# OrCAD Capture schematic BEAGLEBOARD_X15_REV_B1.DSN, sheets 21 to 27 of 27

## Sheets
21 P22_DDR3 BANK 2: size B; title: BeagleBoard-X15 DDR BANK 2; note: BeagleBoard-X15_B.dsn
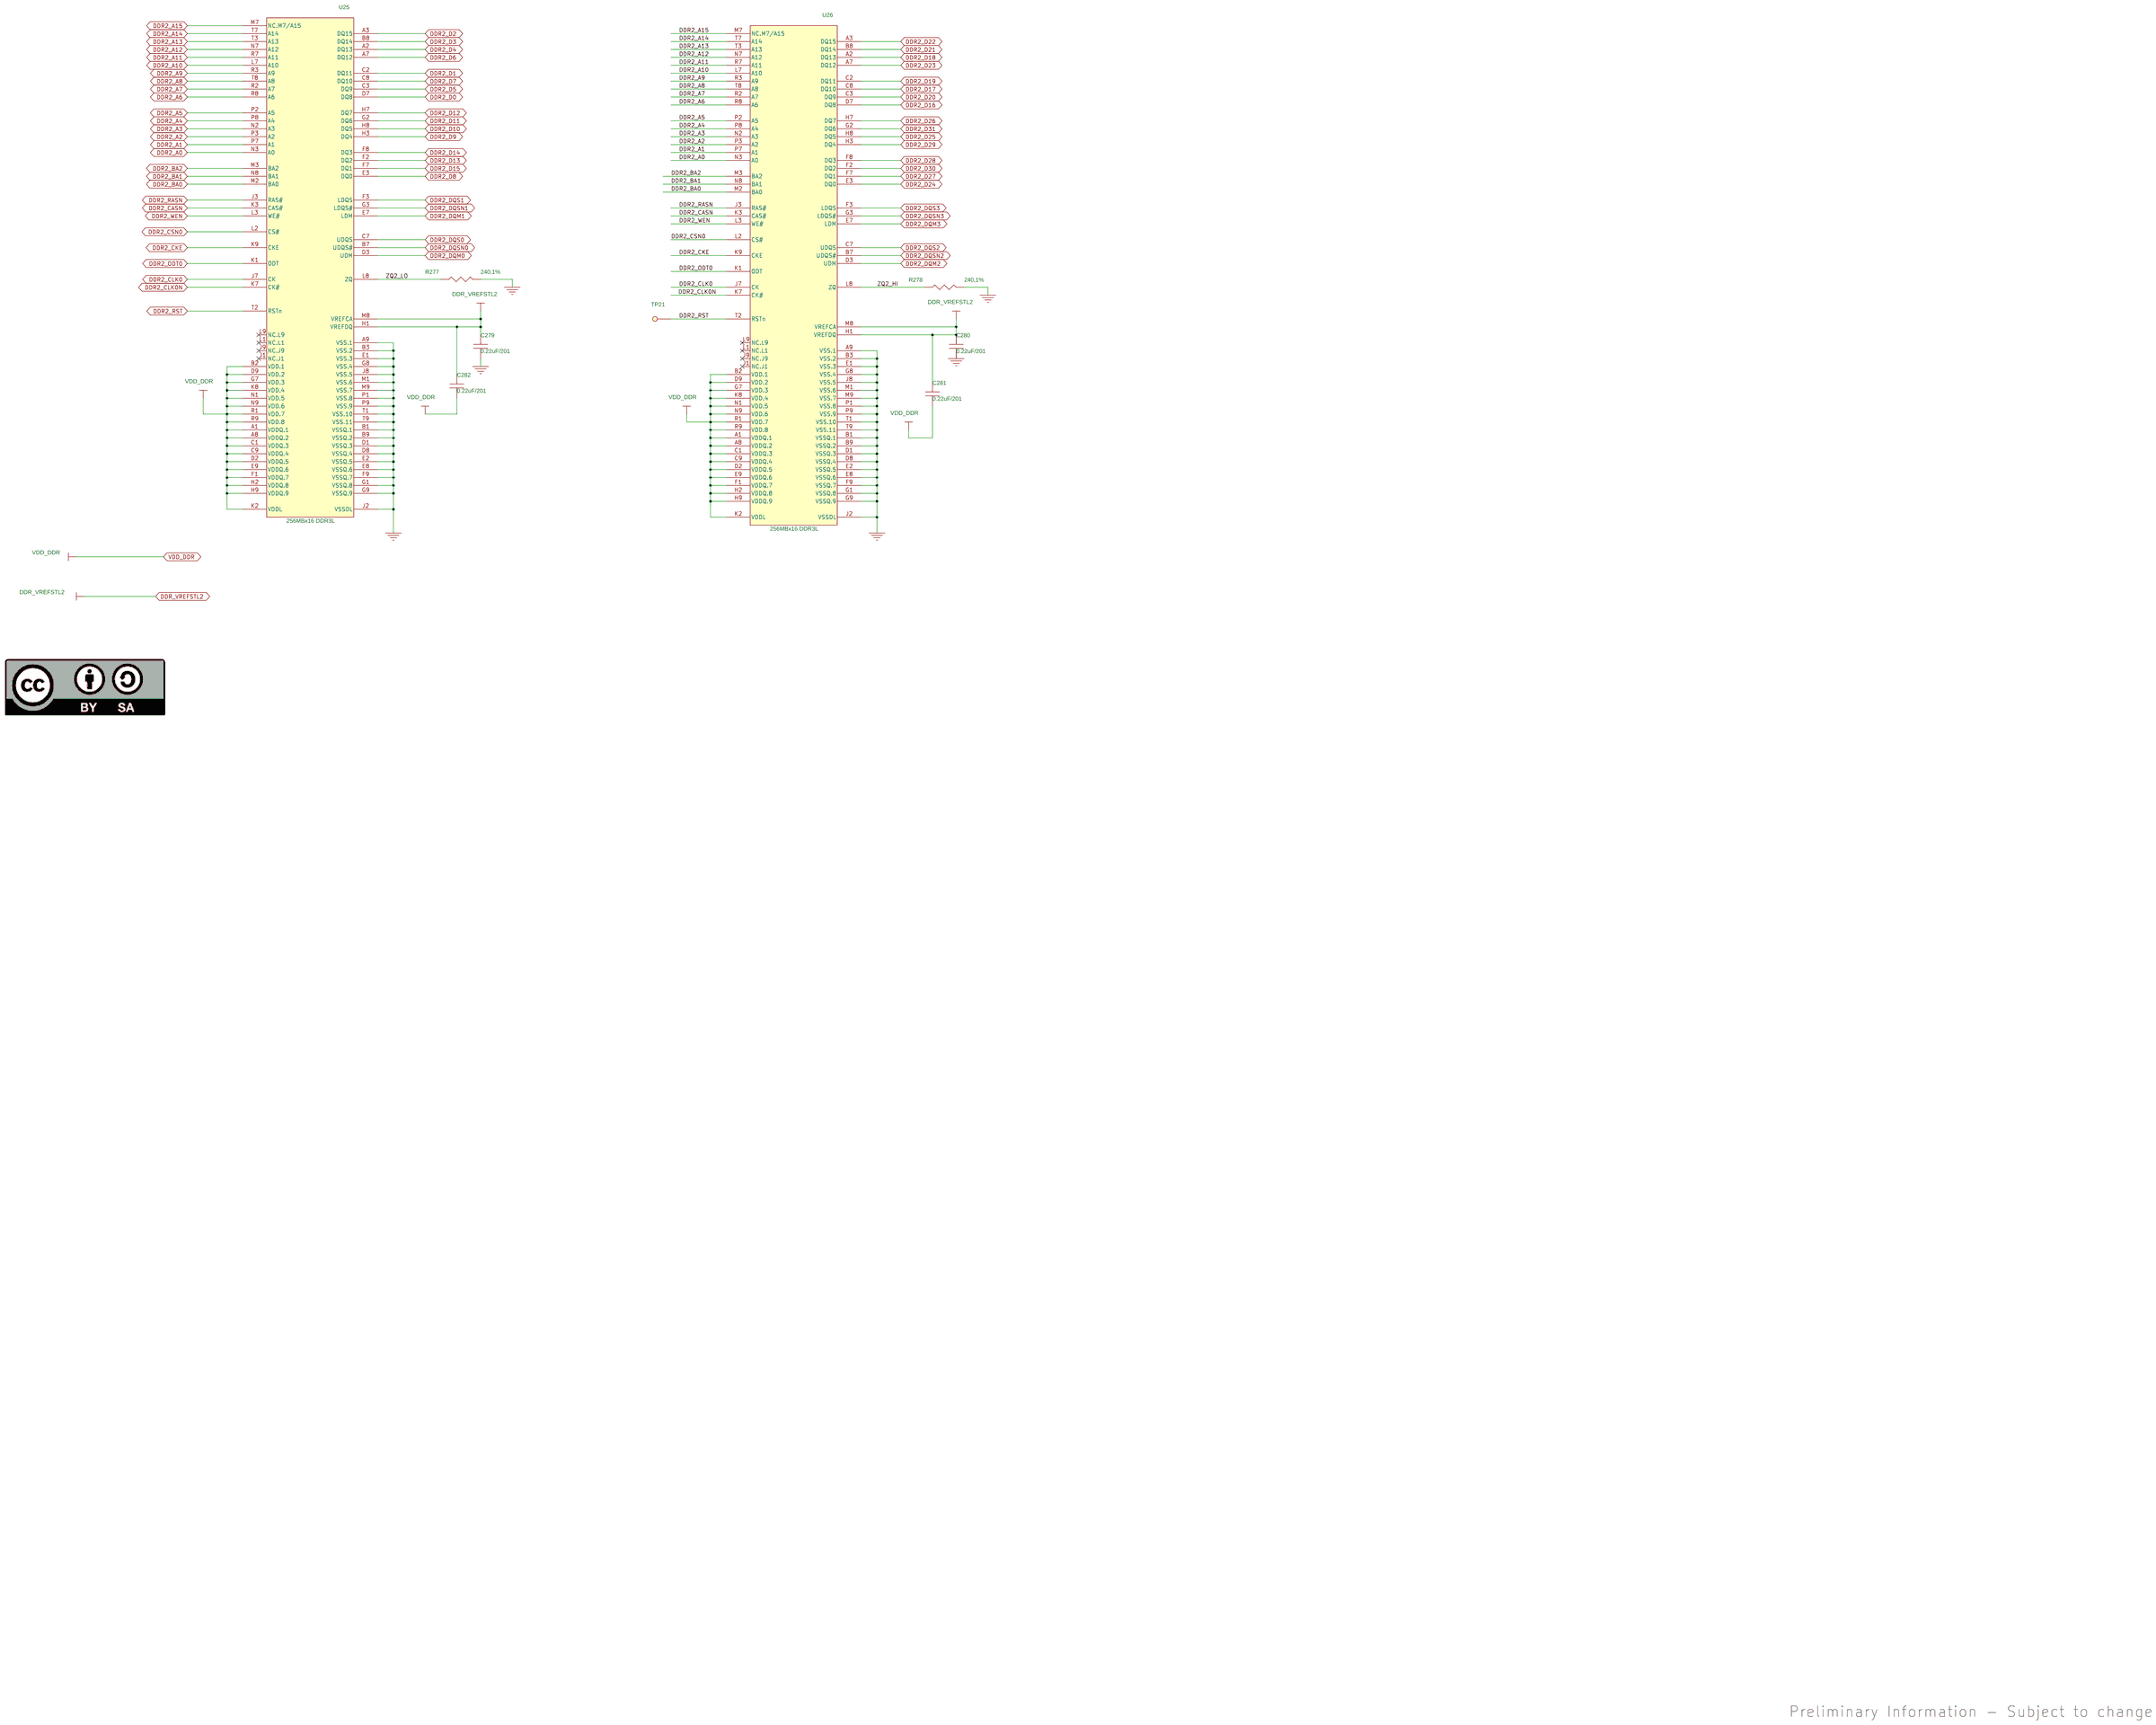
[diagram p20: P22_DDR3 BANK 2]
22 P23_DDR3 BANK 2 CAPS & TERM: size B; title: BEAGLEBOARD-X15 DDR3L BANK 2 CAPS AND TERMINATIONS; note: BeagleBoard-X15_B.dsn
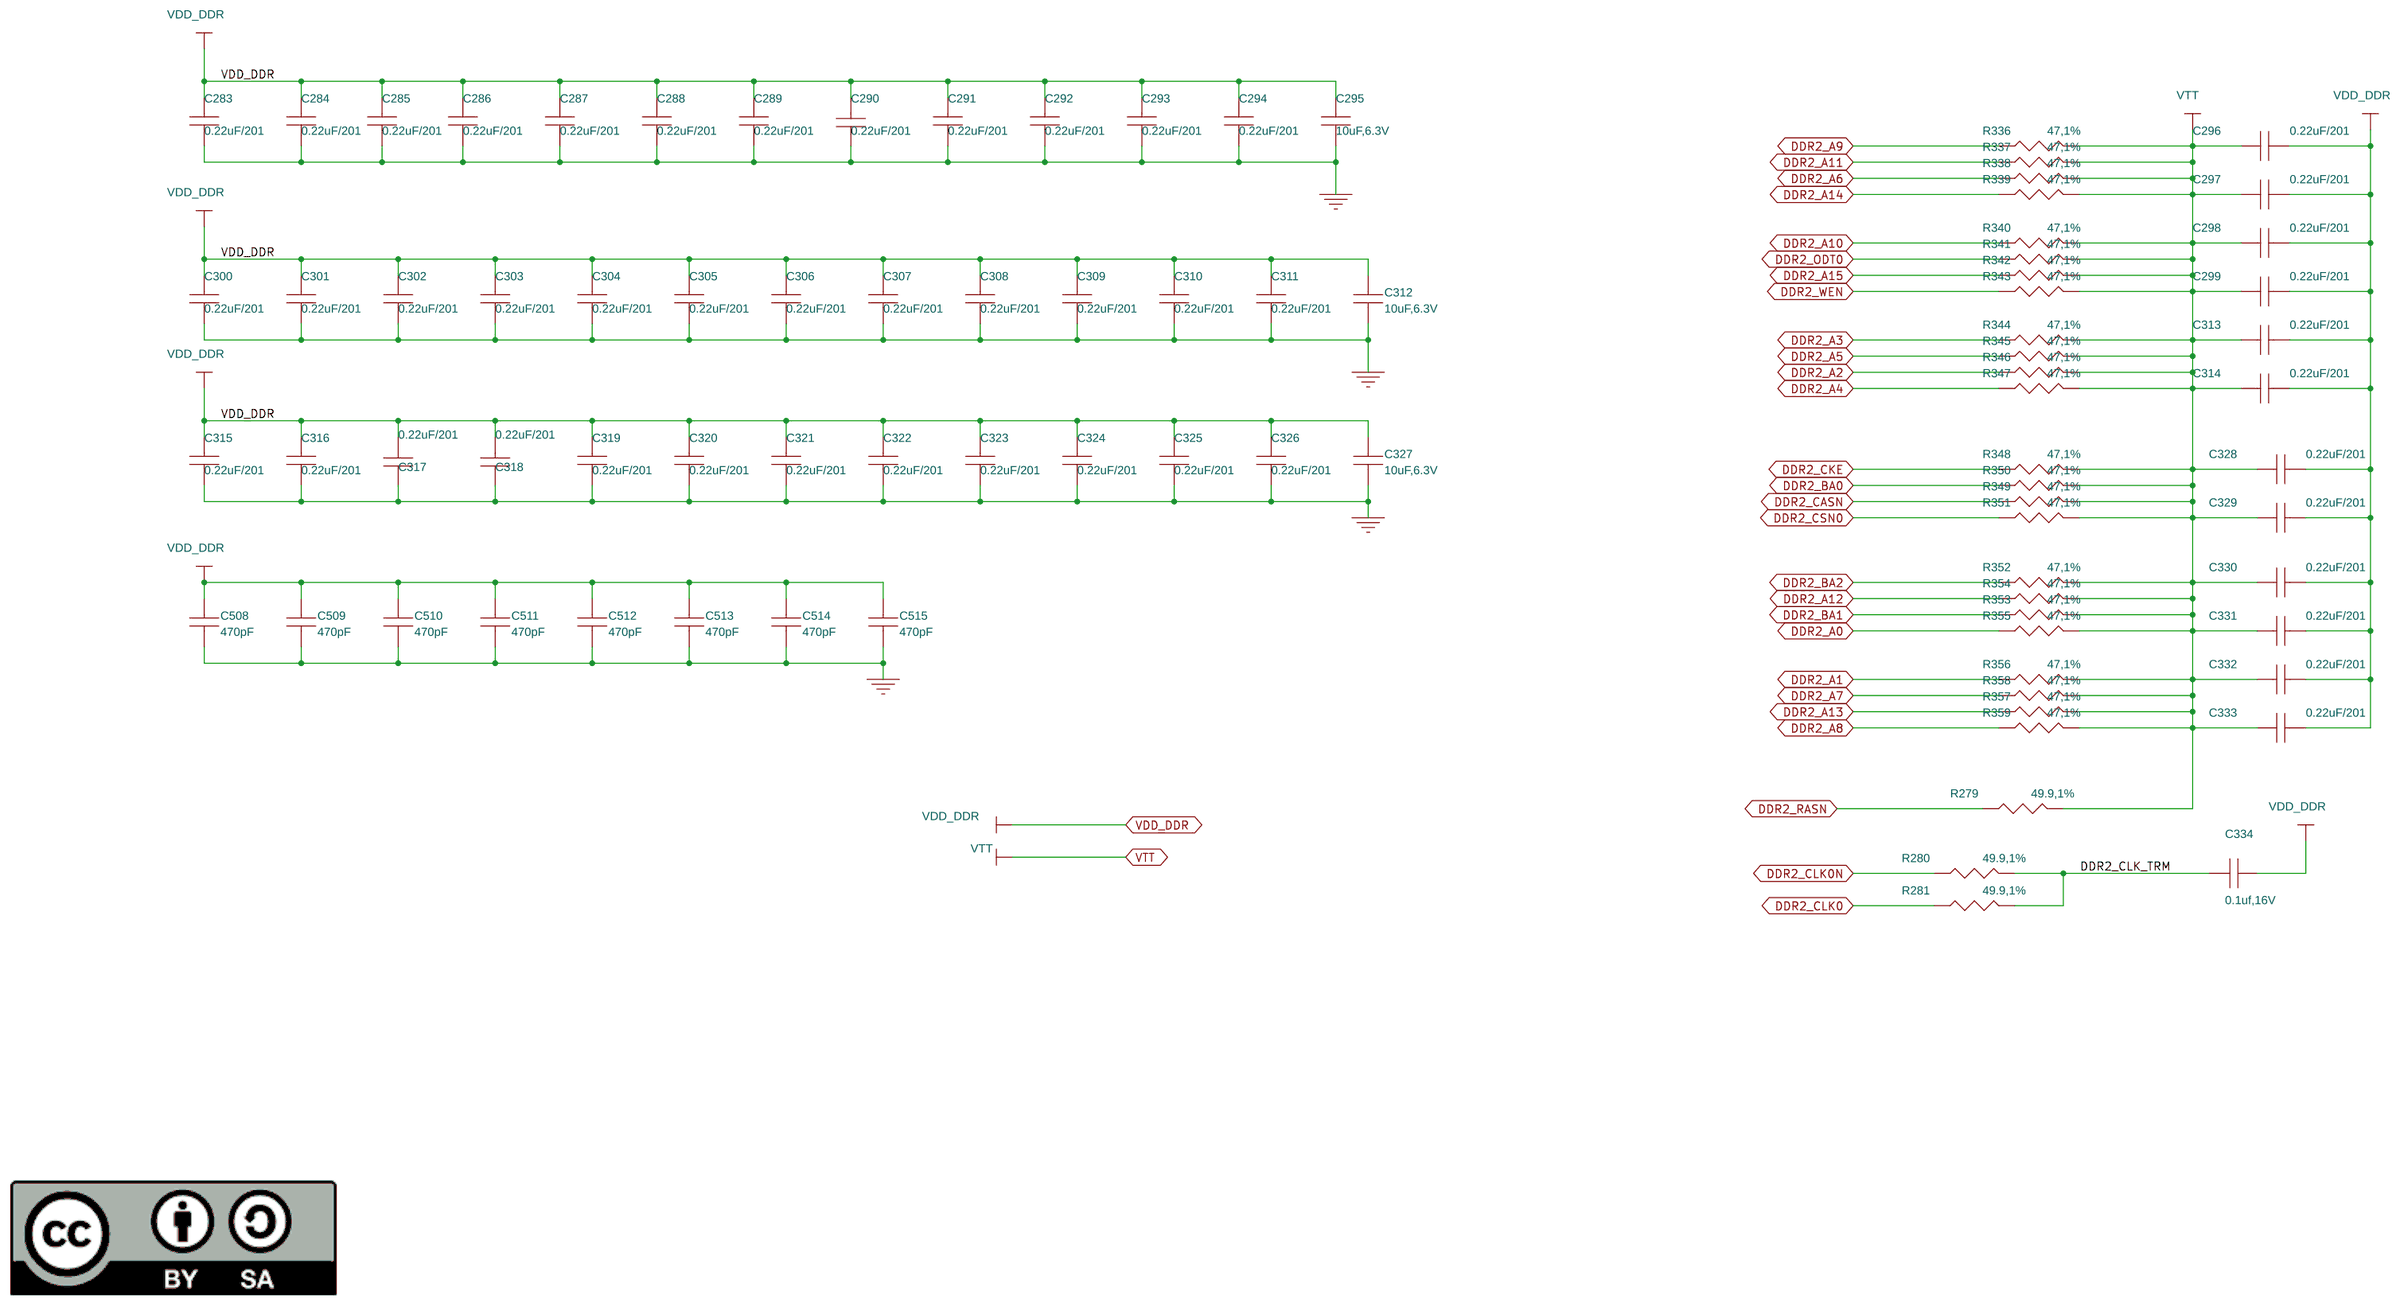
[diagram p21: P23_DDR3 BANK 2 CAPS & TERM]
23 P24_DDR3 BANK1 CAPS & TERM: size B; title: BEAGLEBOARD-X15 DDR3L BANK 1 CAPS AND TERMINATIONS; note: BeagleBoard-X15_B.dsn
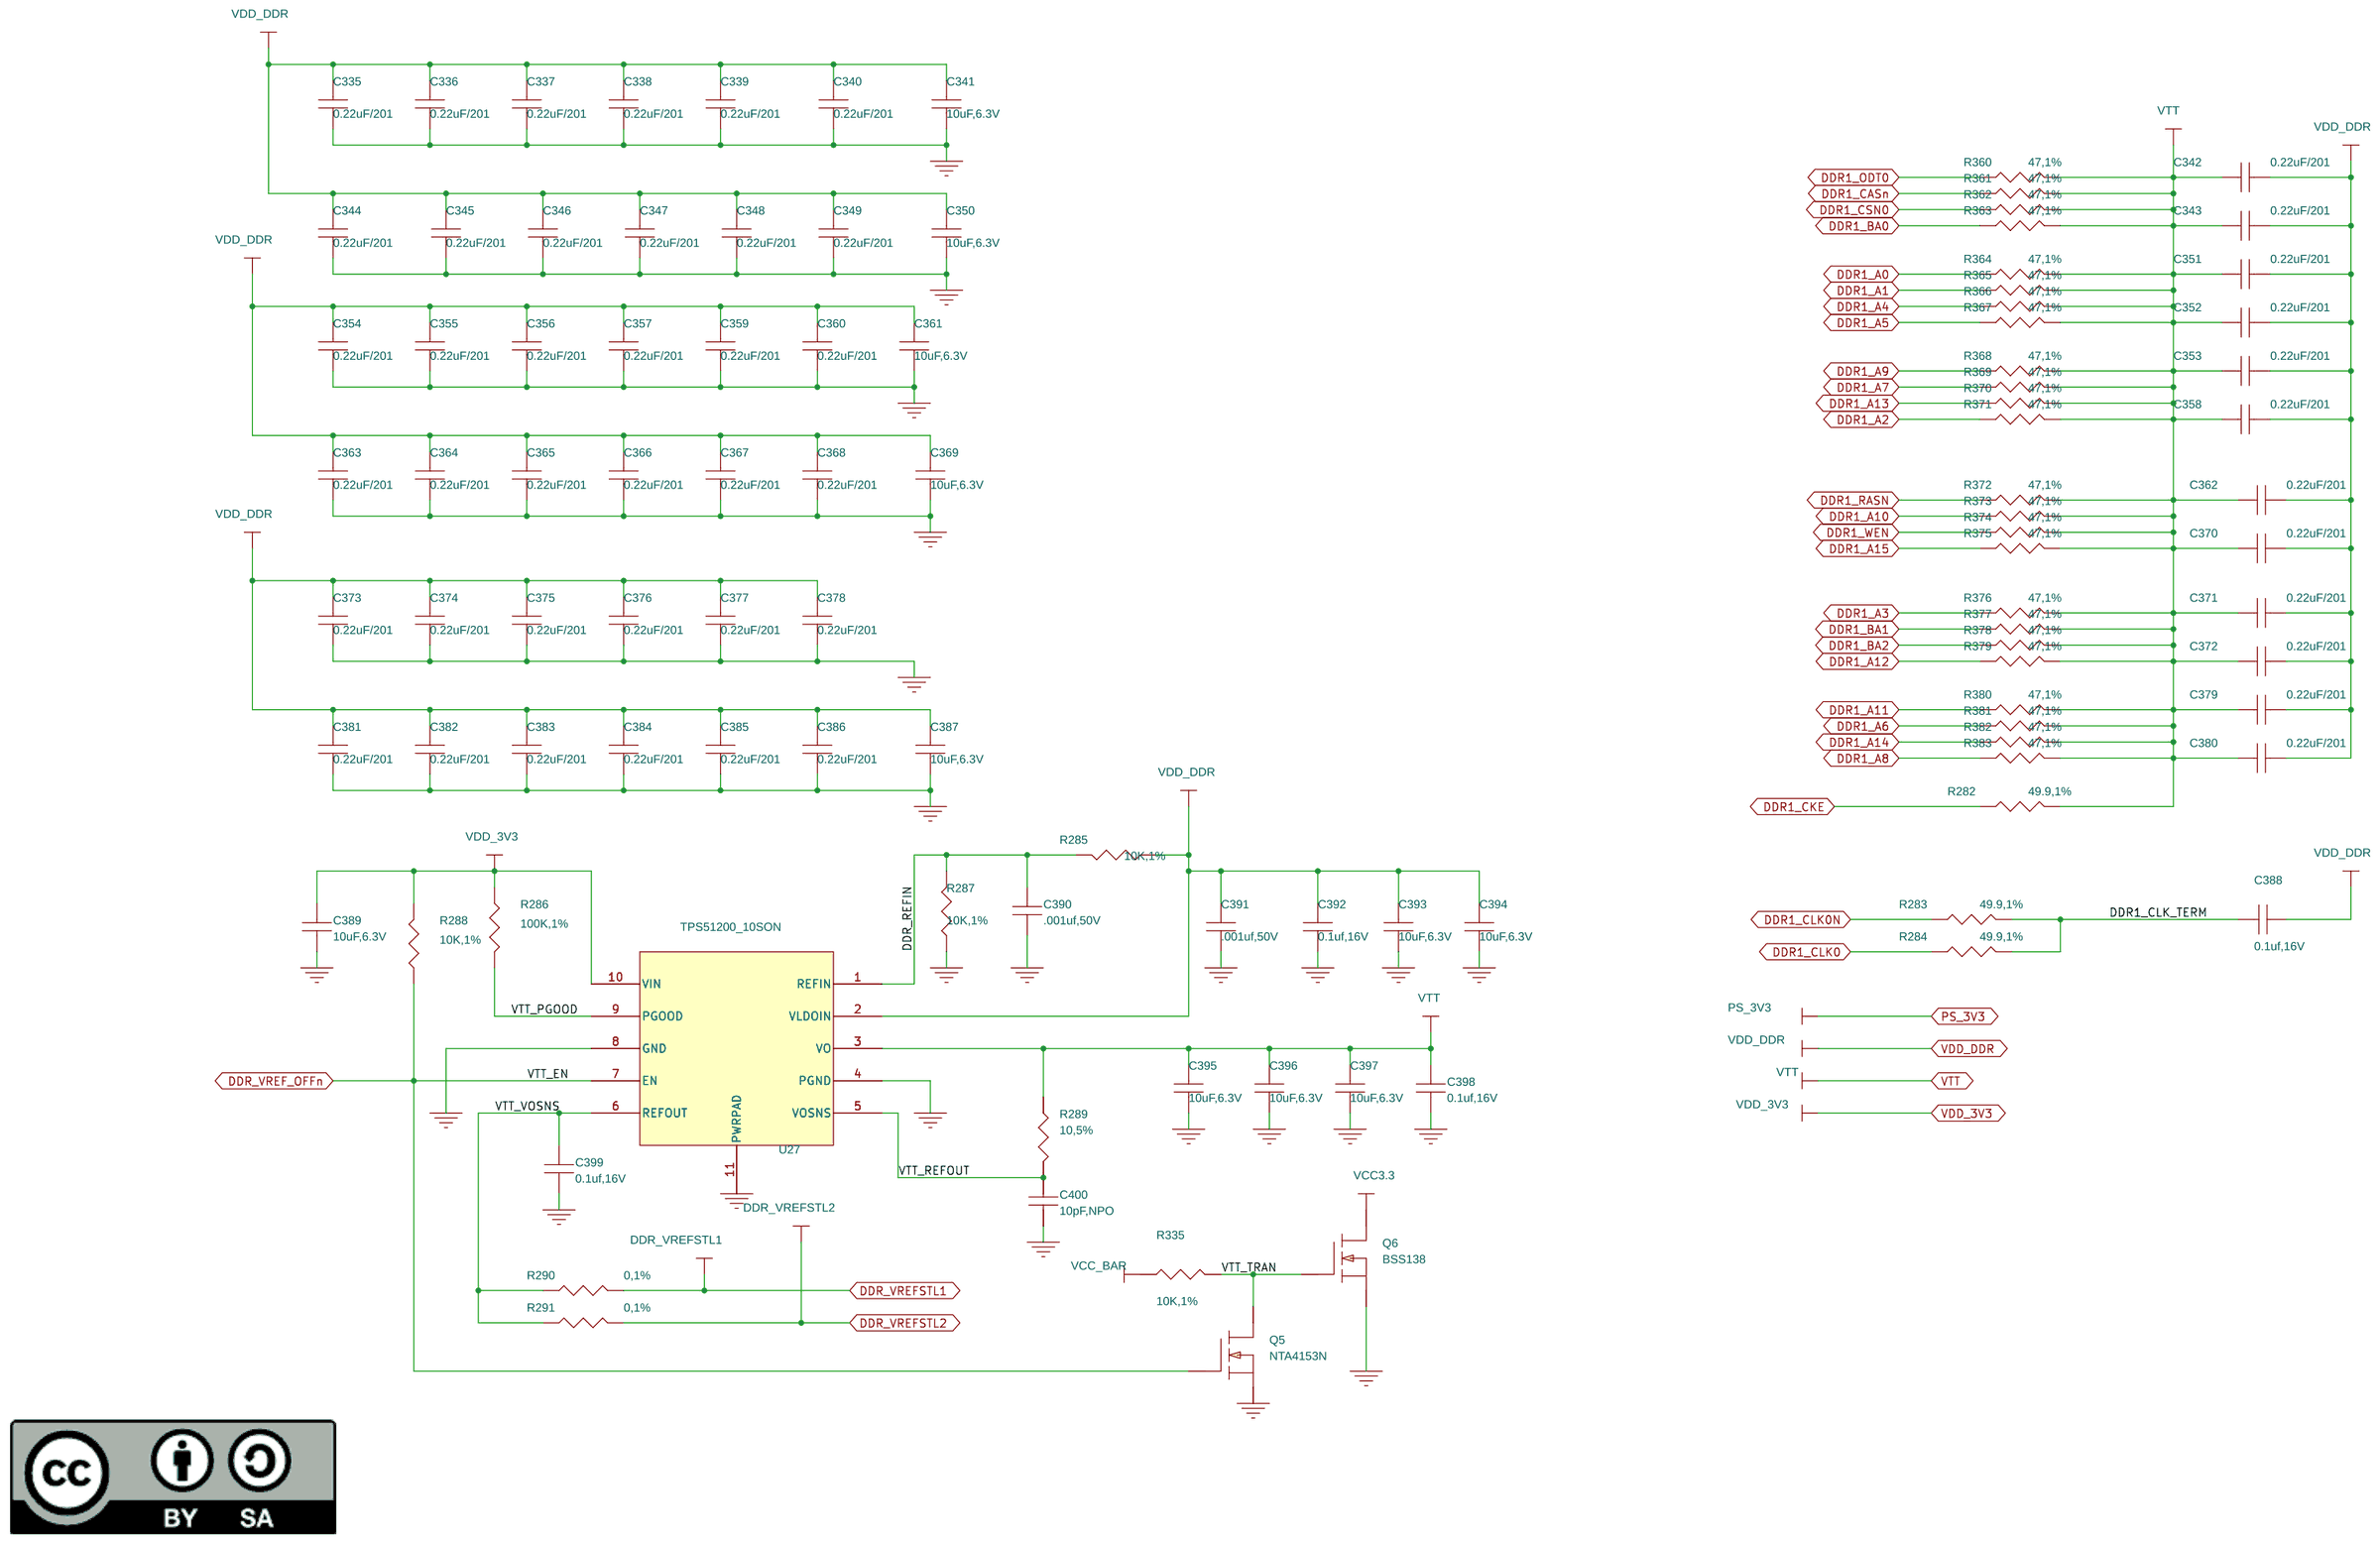
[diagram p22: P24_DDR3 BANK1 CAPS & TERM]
24 P25_USB & eSATA CONNECTORS: size B; title: BEAGLEBOARD-X15 USB POWER & CONNECTORS; note: BeagleBoard-X15_B.dsn
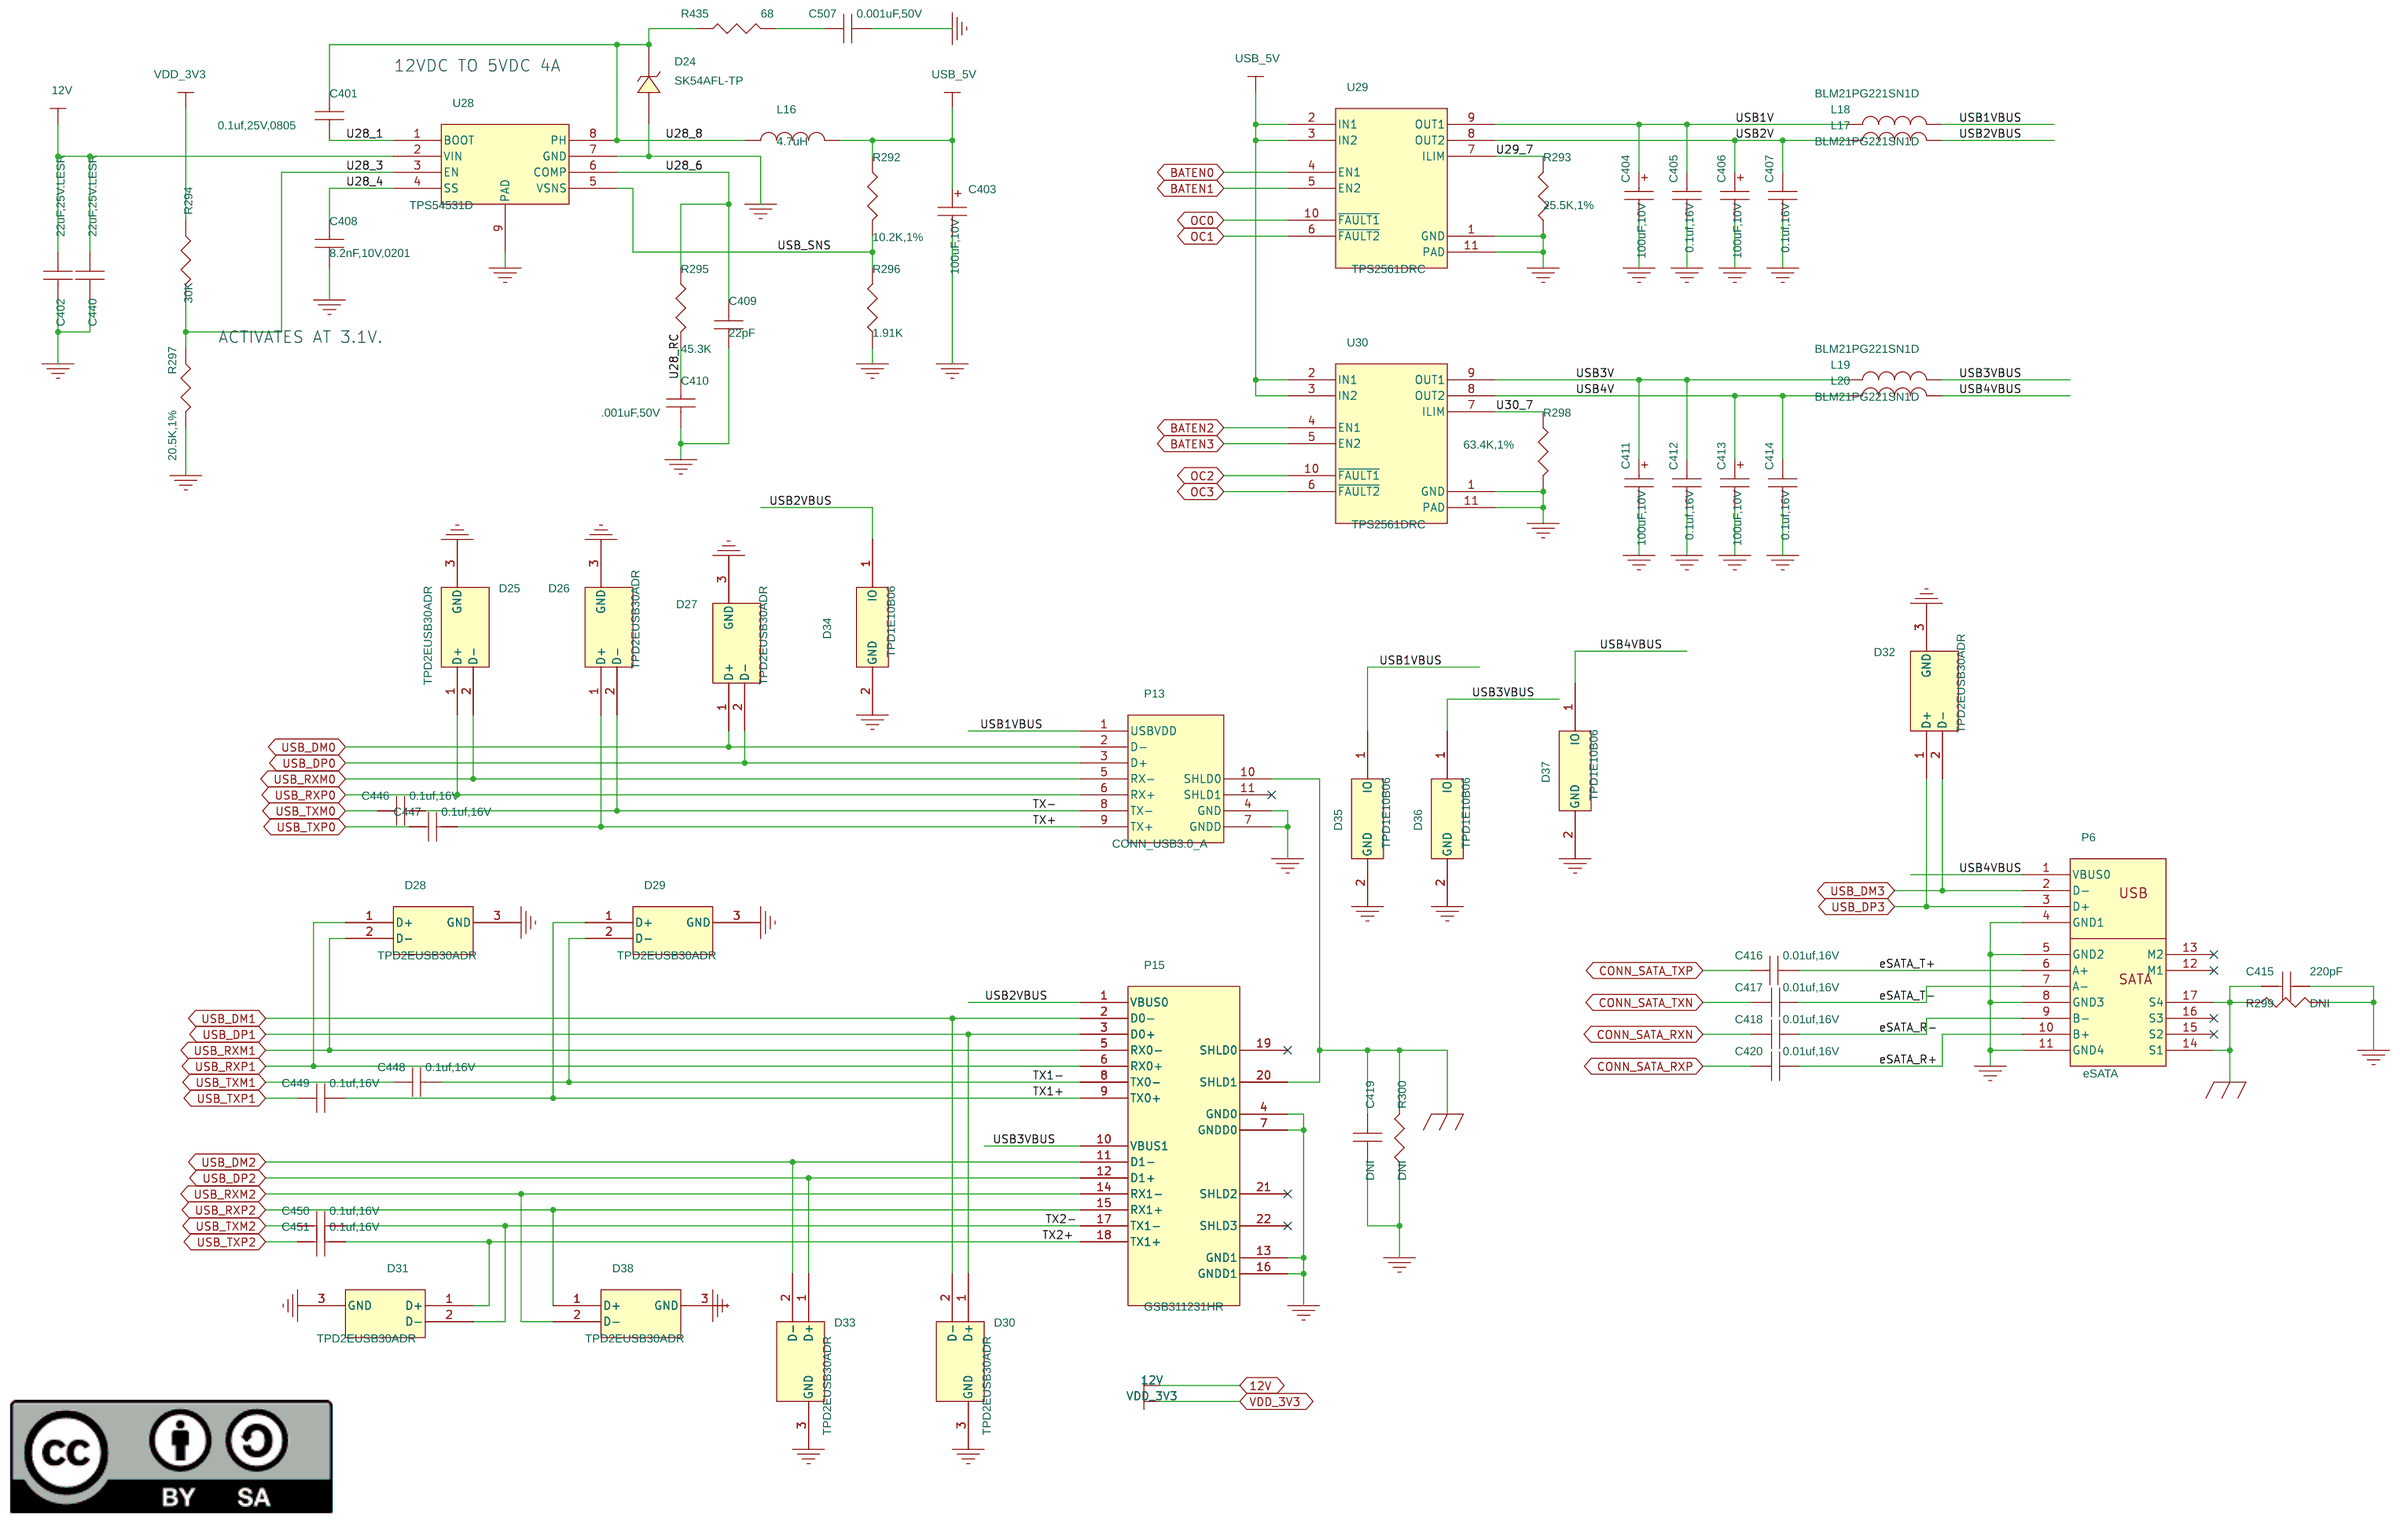
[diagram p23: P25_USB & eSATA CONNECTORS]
25 P26_PCI, SATA, & SERDES CLOCK: size B; title: BEAGLEBOARD-X15 SERDES CLOCK, SATA, AND PCIe; note: BeagleBoard-X15_B.dsn
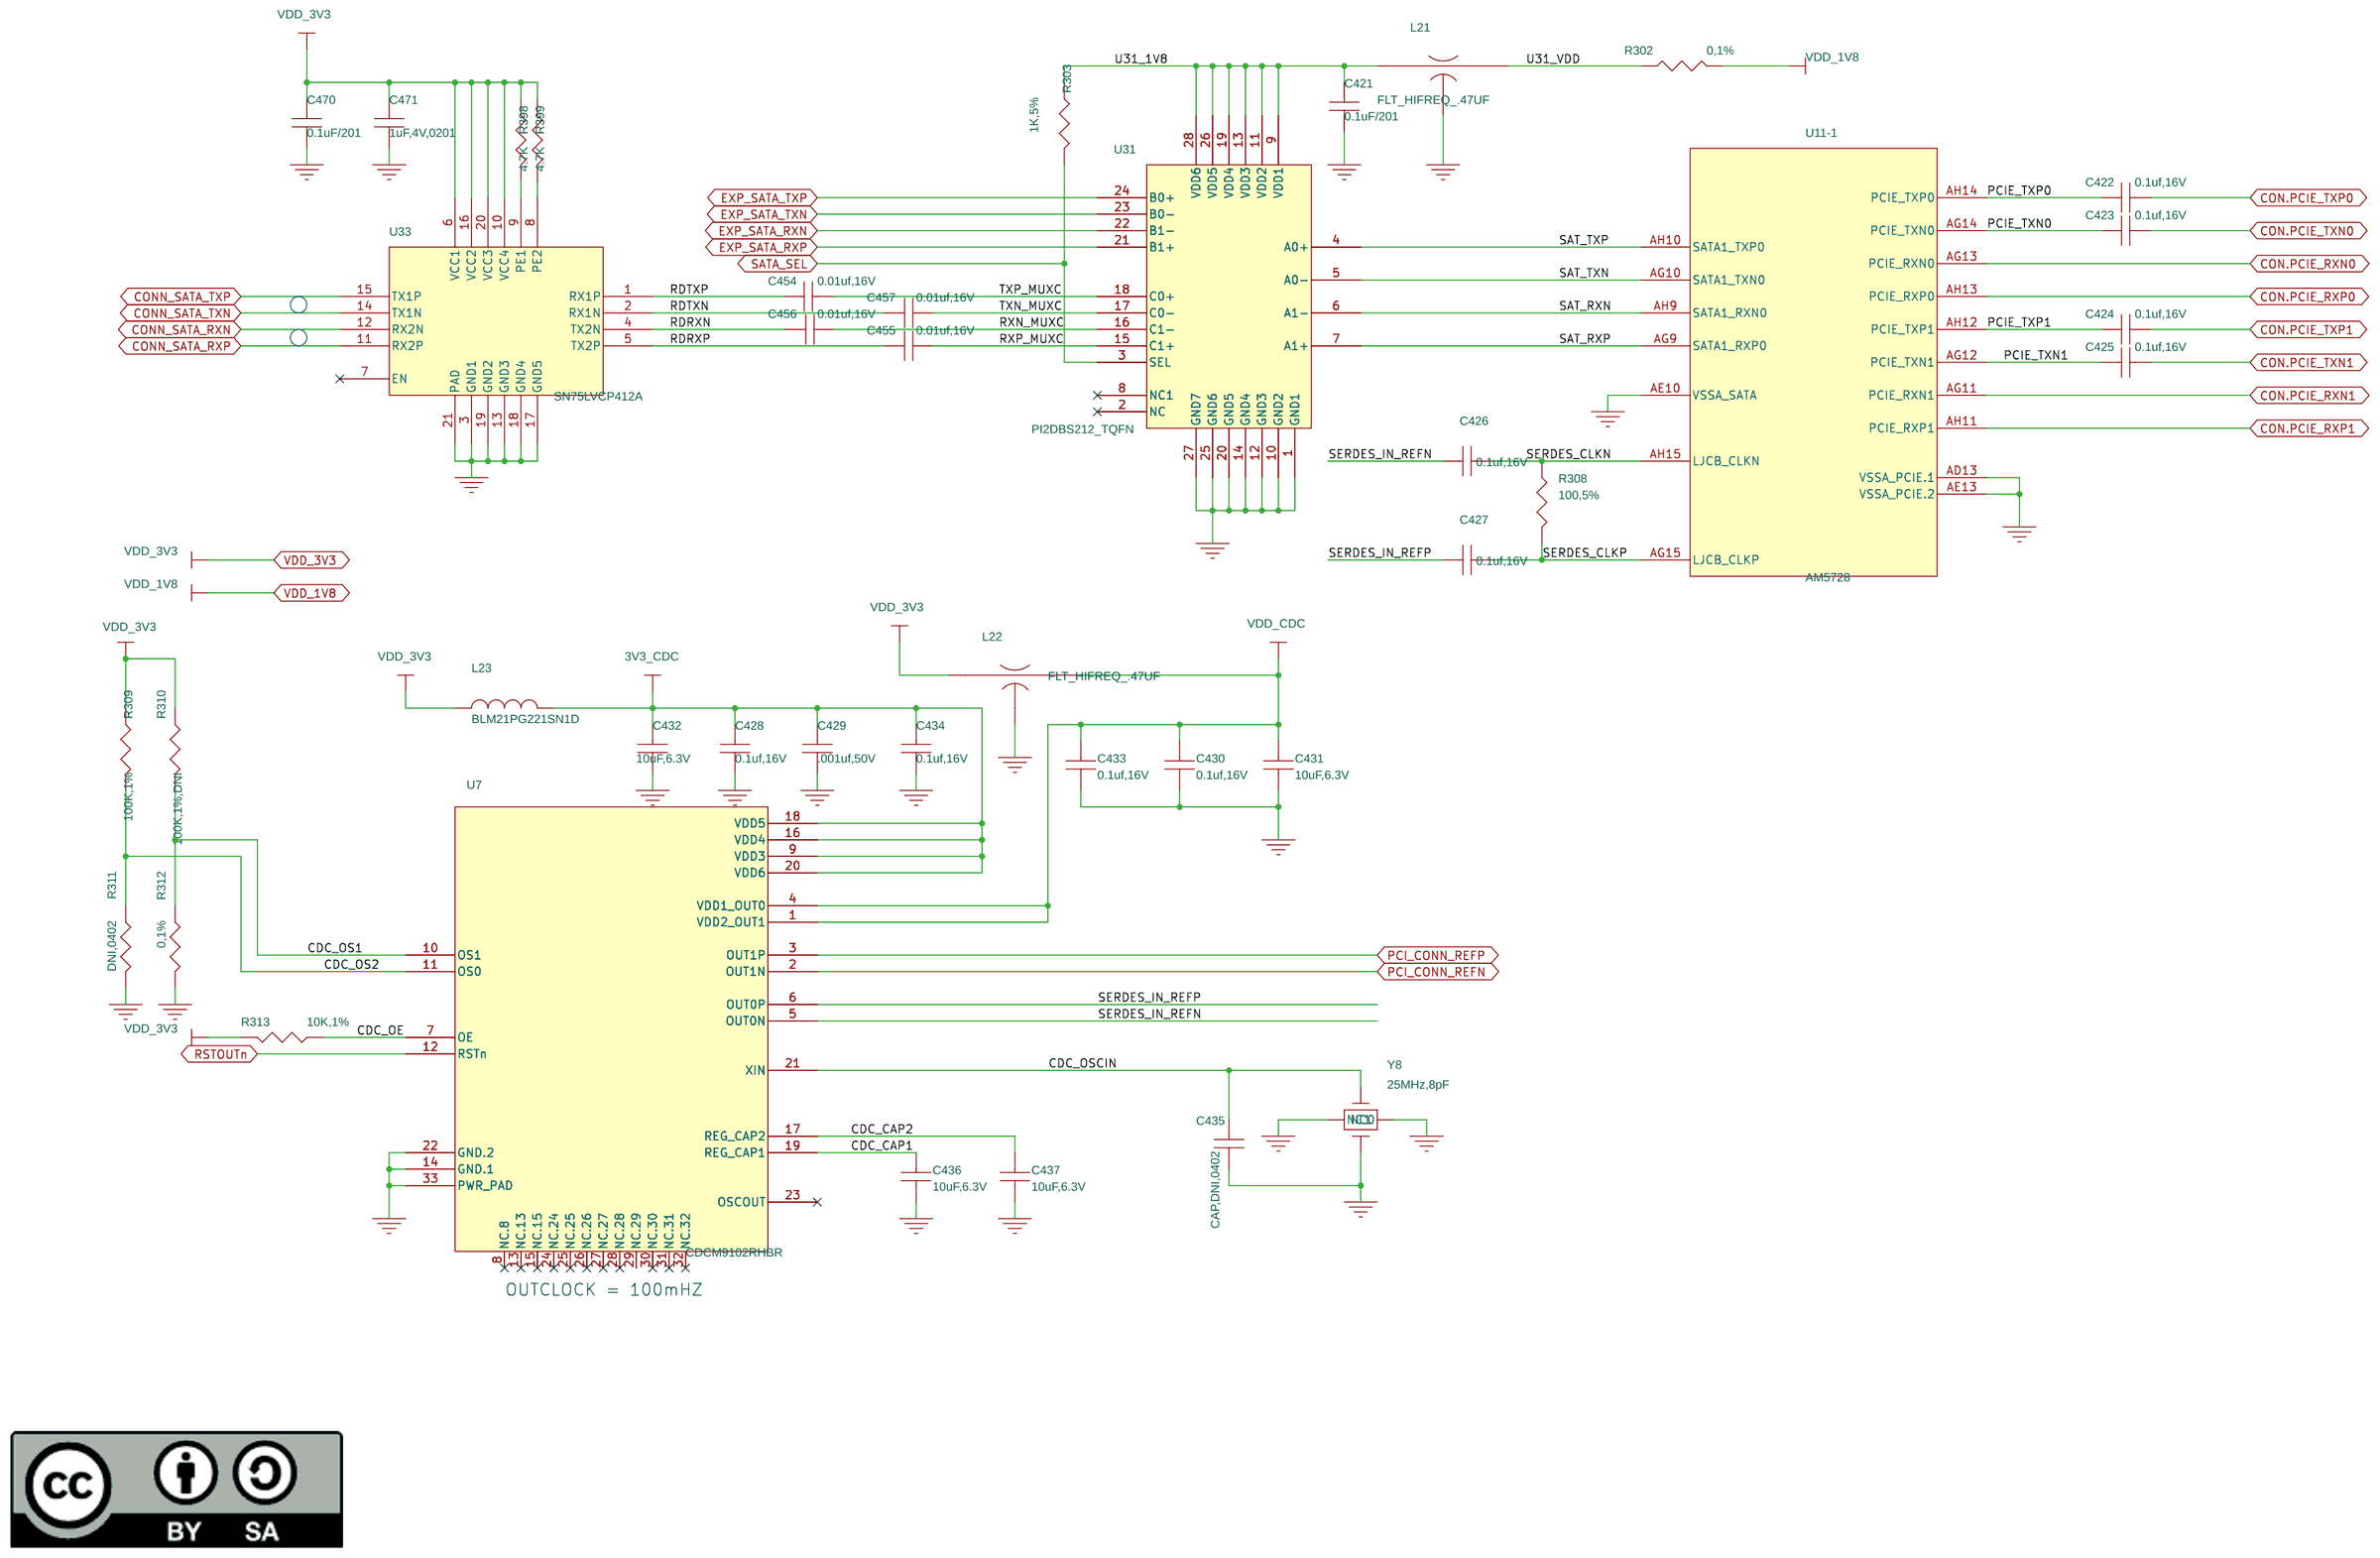
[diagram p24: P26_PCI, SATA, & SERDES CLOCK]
26 P27_EXPANSION HEADERS: size B; title: BEAGLEBOARD-X15 EXPANSION CONNECTORS; note: BeagleBoard-X15_B.dsn
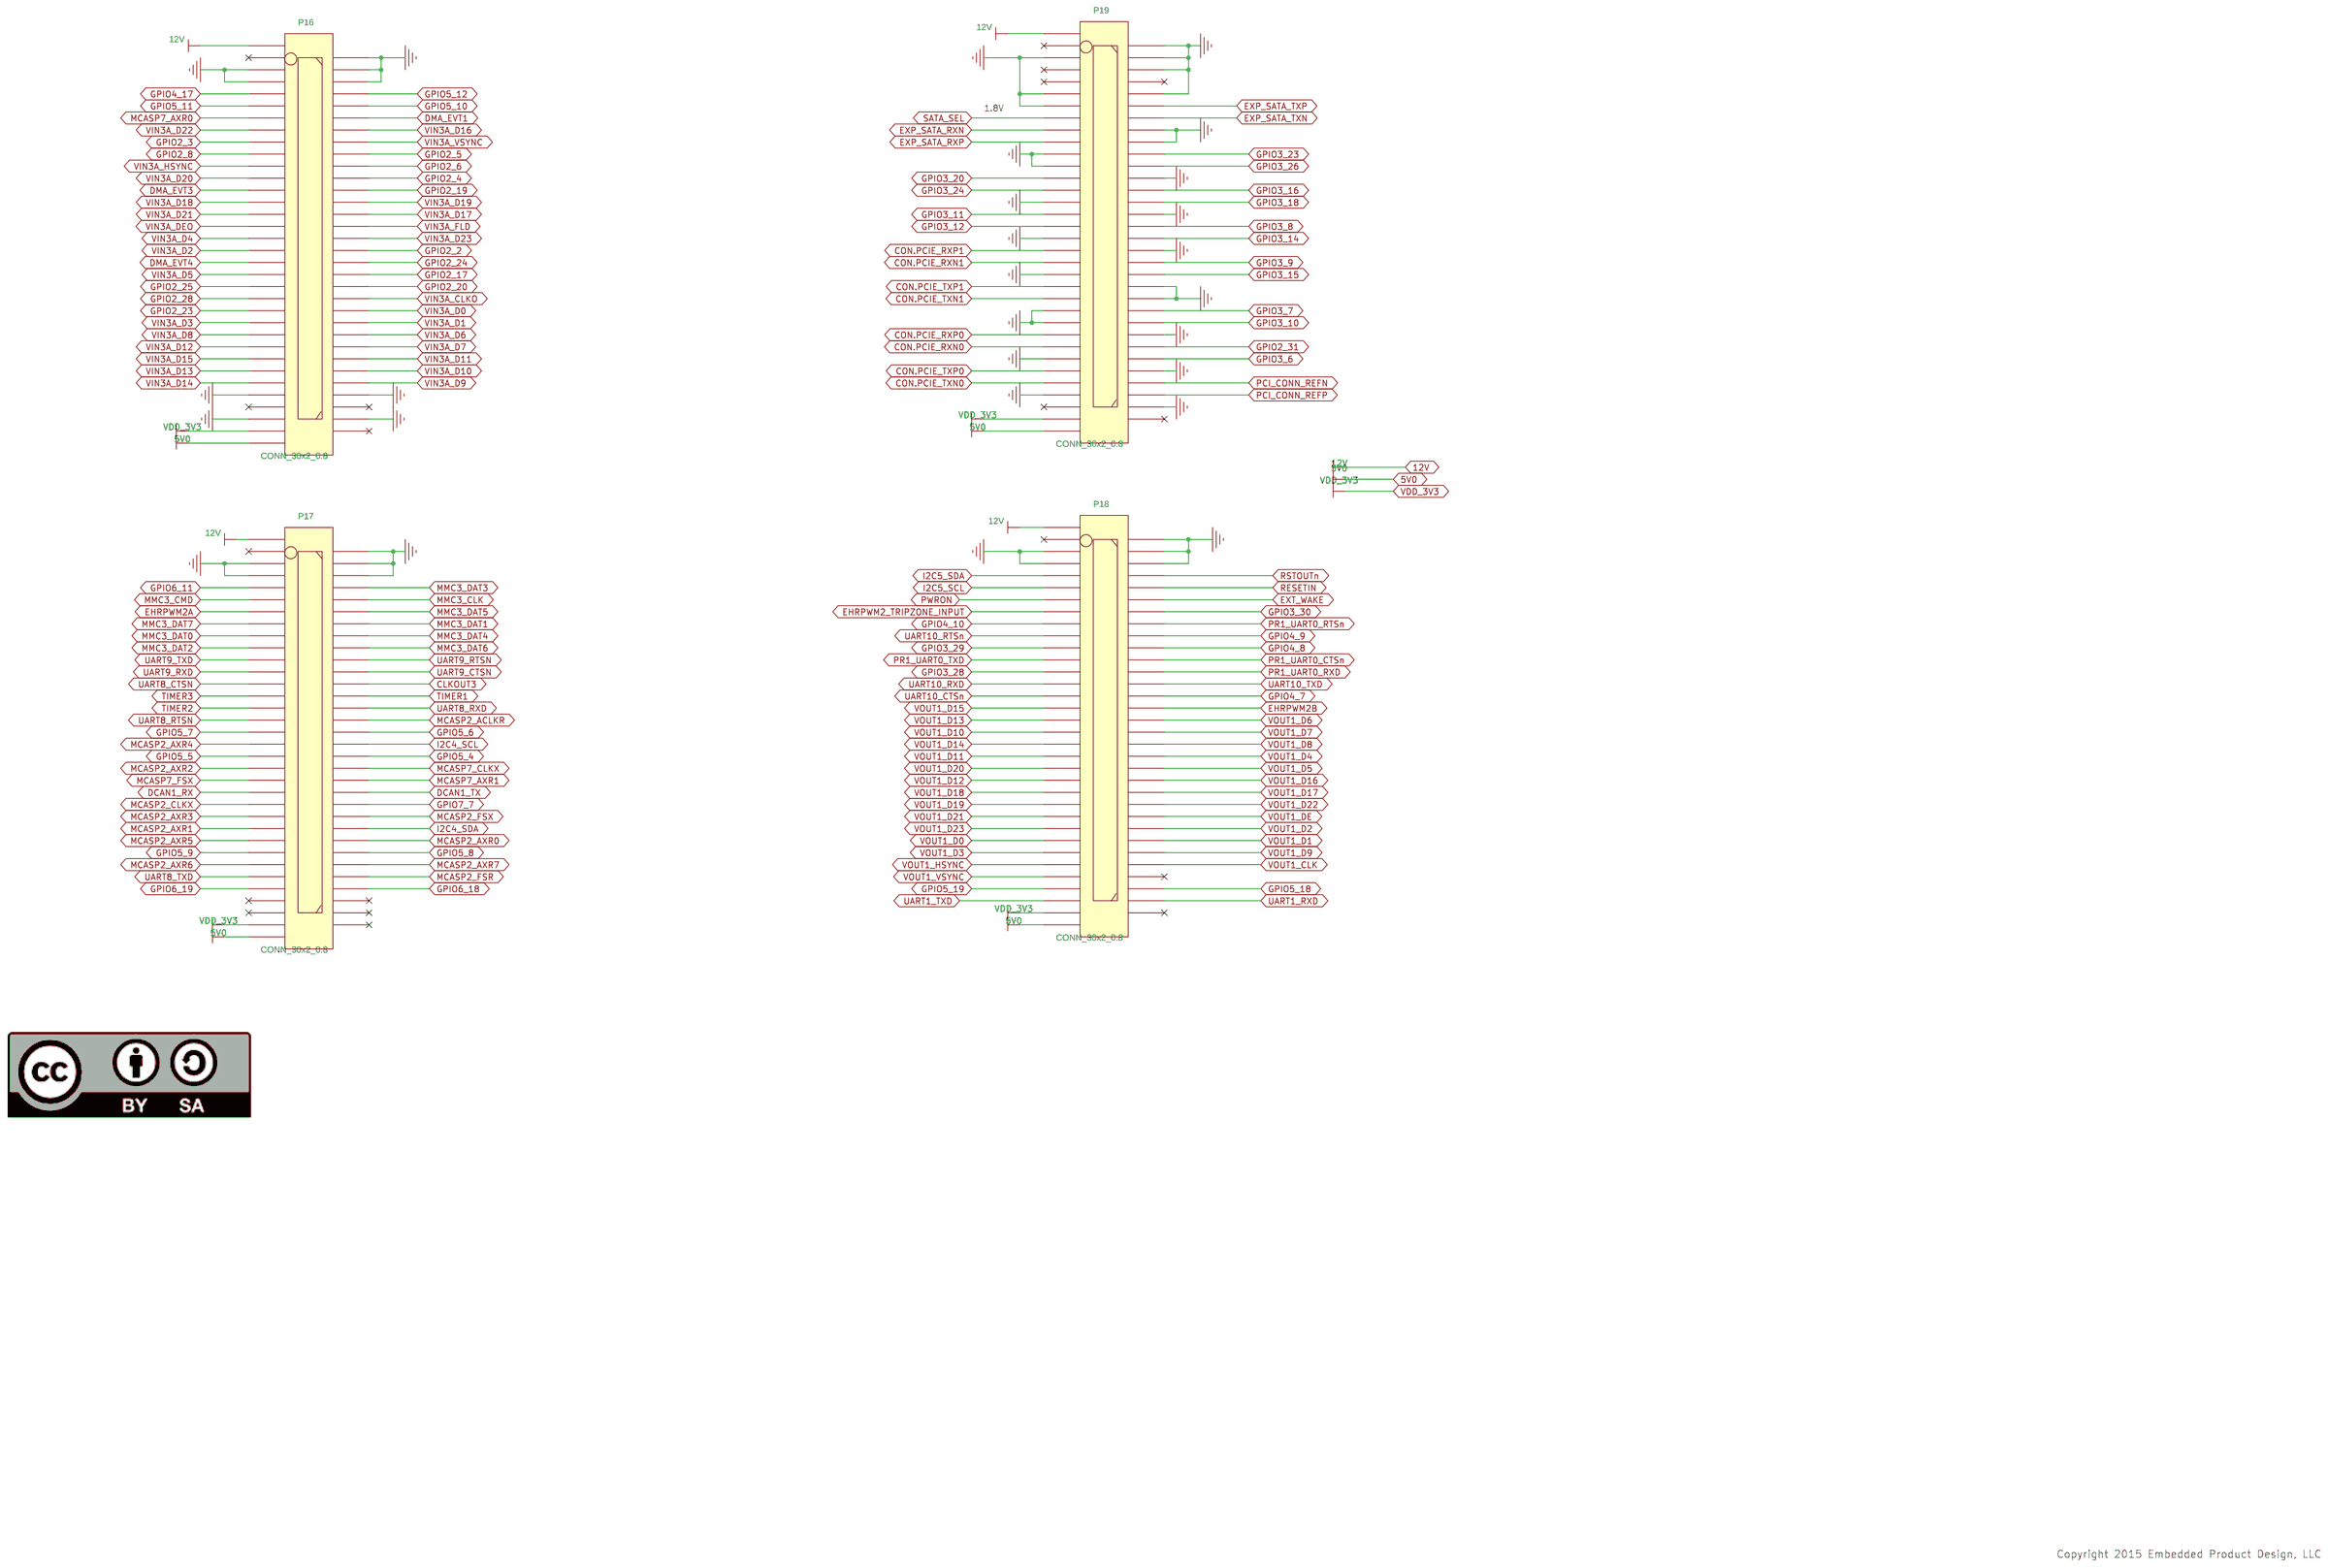
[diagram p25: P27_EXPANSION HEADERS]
27 P15_AM572x I/O, LEDS, GPIO: size B; title: BeagleBoard-X15 AM5728 I/O & LEDS; note: BeagleBoard-X15_B.dsn
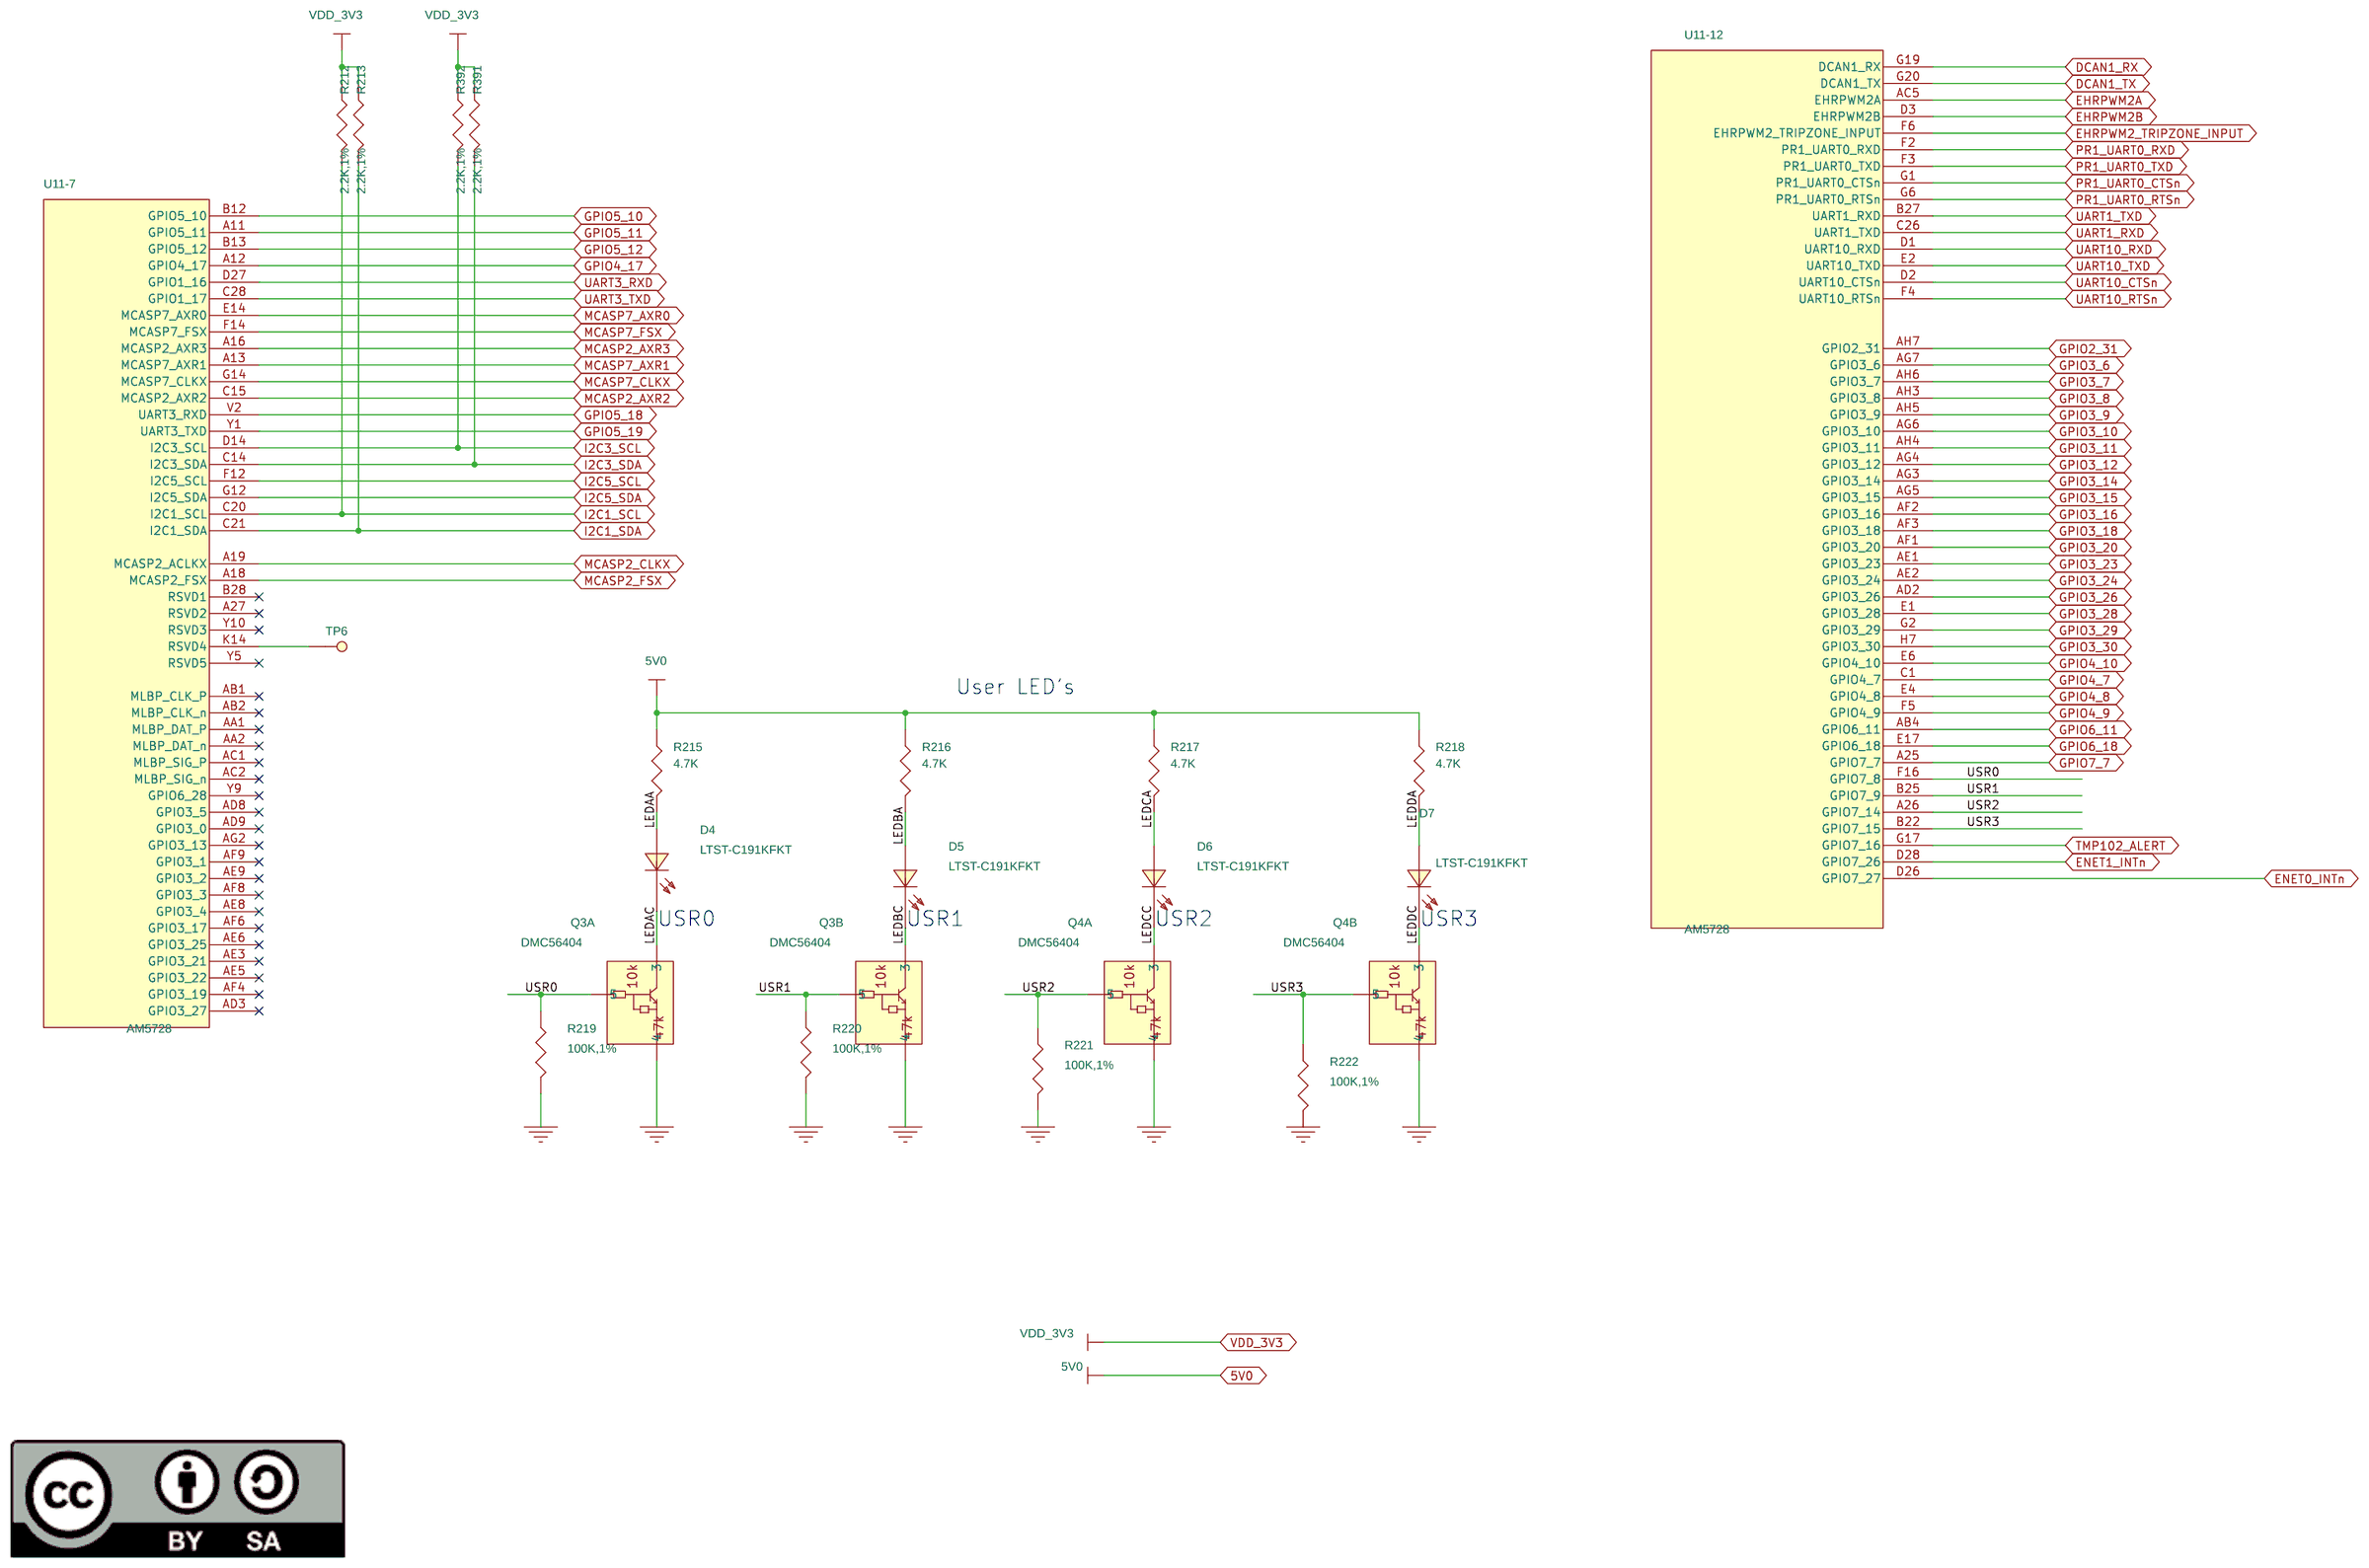
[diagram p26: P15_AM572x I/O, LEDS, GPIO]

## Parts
sheet P15_AM572x I/O, LEDS, GPIO
D4  LTST-C191KFKT  [LED_603]
D5  LTST-C191KFKT  [LED_603]
D6  LTST-C191KFKT  [LED_603]
D7  LTST-C191KFKT  [LED_603]
Q3  DMC56404  [SMINI6-F3-B]  (sections A,B)
Q4  DMC56404  [SMINI6-F3-B]  (sections A,B)
R212  2.2K,1%  [402]
R213  2.2K,1%  [402]
R215  4.7K  [402]
R216  4.7K  [402]
R217  4.7K  [402]
R218  4.7K  [402]
R219  100K,1%  [402]
R220  100K,1%  [402]
R221  100K,1%  [402]
R222  100K,1%  [402]
R391  2.2K,1%  [402]
R392  2.2K,1%  [402]
TP6  TP  [TP30C12D]
sheet P16_AM572x, AUDIO, & DEBUG
U11  AM5728  [sktbga-zkk-6334-p760]  (sections -1,-10,-11,-12,-13,-14,-15,-16,-17,-18,-19,-2,-3,-4,-5,-6,-7,-8,-9)
sheet P22_DDR3 BANK 2
C279  0.22uF/201  [201]
C280  0.22uF/201  [201]
C281  0.22uF/201  [201]
C282  0.22uF/201  [201]
R277  240,1%  [402]
R278  240,1%  [402]
TP21  TP  [TP30C12D]
U25  256MBx16 DDR3L  [BGA96_T9_P8_9X14]
U26  256MBx16 DDR3L  [BGA96_T9_P8_9X14]
sheet P23_DDR3 BANK 2 CAPS & TERM
C283  0.22uF/201  [201]
C284  0.22uF/201  [201]
C285  0.22uF/201  [201]
C286  0.22uF/201  [201]
C287  0.22uF/201  [201]
C288  0.22uF/201  [201]
C289  0.22uF/201  [201]
C290  0.22uF/201  [201]
C291  0.22uF/201  [201]
C292  0.22uF/201  [201]
C293  0.22uF/201  [201]
C294  0.22uF/201  [201]
C295  10uF,6.3V  [603]
C296  0.22uF/201  [201]
C297  0.22uF/201  [201]
C298  0.22uF/201  [201]
C299  0.22uF/201  [201]
C300  0.22uF/201  [201]
C301  0.22uF/201  [201]
C302  0.22uF/201  [201]
C303  0.22uF/201  [201]
C304  0.22uF/201  [201]
C305  0.22uF/201  [201]
C306  0.22uF/201  [201]
C307  0.22uF/201  [201]
C308  0.22uF/201  [201]
C309  0.22uF/201  [201]
C310  0.22uF/201  [201]
C311  0.22uF/201  [201]
C312  10uF,6.3V  [603]
C313  0.22uF/201  [201]
C314  0.22uF/201  [201]
C315  0.22uF/201  [201]
C316  0.22uF/201  [201]
C317  0.22uF/201  [201]
C318  0.22uF/201  [201]
C319  0.22uF/201  [201]
C320  0.22uF/201  [201]
C321  0.22uF/201  [201]
C322  0.22uF/201  [201]
C323  0.22uF/201  [201]
C324  0.22uF/201  [201]
C325  0.22uF/201  [201]
C326  0.22uF/201  [201]
C327  10uF,6.3V  [603]
C328  0.22uF/201  [201]
C329  0.22uF/201  [201]
C330  0.22uF/201  [201]
C331  0.22uF/201  [201]
C332  0.22uF/201  [201]
C333  0.22uF/201  [201]
C334  0.1uf,16V  [402]
C508  470pF  [201]
C509  470pF  [201]
C510  470pF  [201]
C511  470pF  [201]
C512  470pF  [201]
C513  470pF  [201]
C514  470pF  [201]
C515  470pF  [201]
R279  49.9,1%  [402]
R280  49.9,1%  [402]
R281  49.9,1%  [402]
R336  47,1%  [402]
R337  47,1%  [402]
R338  47,1%  [402]
R339  47,1%  [402]
R340  47,1%  [402]
R341  47,1%  [402]
R342  47,1%  [402]
R343  47,1%  [402]
R344  47,1%  [402]
R345  47,1%  [402]
R346  47,1%  [402]
R347  47,1%  [402]
R348  47,1%  [402]
R349  47,1%  [402]
R350  47,1%  [402]
R351  47,1%  [402]
R352  47,1%  [402]
R353  47,1%  [402]
R354  47,1%  [402]
R355  47,1%  [402]
R356  47,1%  [402]
R357  47,1%  [402]
R358  47,1%  [402]
R359  47,1%  [402]
sheet P24_DDR3 BANK1 CAPS & TERM
C335  0.22uF/201  [201]
C336  0.22uF/201  [201]
C337  0.22uF/201  [201]
C338  0.22uF/201  [201]
C339  0.22uF/201  [201]
C340  0.22uF/201  [201]
C341  10uF,6.3V  [603]
C342  0.22uF/201  [201]
C343  0.22uF/201  [201]
C344  0.22uF/201  [201]
C345  0.22uF/201  [201]
C346  0.22uF/201  [201]
C347  0.22uF/201  [201]
C348  0.22uF/201  [201]
C349  0.22uF/201  [201]
C350  10uF,6.3V  [603]
C351  0.22uF/201  [201]
C352  0.22uF/201  [201]
C353  0.22uF/201  [201]
C354  0.22uF/201  [201]
C355  0.22uF/201  [201]
C356  0.22uF/201  [201]
C357  0.22uF/201  [201]
C358  0.22uF/201  [201]
C359  0.22uF/201  [201]
C360  0.22uF/201  [201]
C361  10uF,6.3V  [603]
C362  0.22uF/201  [201]
C363  0.22uF/201  [201]
C364  0.22uF/201  [201]
C365  0.22uF/201  [201]
C366  0.22uF/201  [201]
C367  0.22uF/201  [201]
C368  0.22uF/201  [201]
C369  10uF,6.3V  [603]
C370  0.22uF/201  [201]
C371  0.22uF/201  [201]
C372  0.22uF/201  [201]
C373  0.22uF/201  [201]
C374  0.22uF/201  [201]
C375  0.22uF/201  [201]
C376  0.22uF/201  [201]
C377  0.22uF/201  [201]
C378  0.22uF/201  [201]
C379  0.22uF/201  [201]
C380  0.22uF/201  [201]
C381  0.22uF/201  [201]
C382  0.22uF/201  [201]
C383  0.22uF/201  [201]
C384  0.22uF/201  [201]
C385  0.22uF/201  [201]
C386  0.22uF/201  [201]
C387  10uF,6.3V  [603]
C388  0.1uf,16V  [402]
C389  10uF,6.3V  [603]
C390  .001uf,50V  [402]
C391  .001uf,50V  [402]
C392  0.1uf,16V  [402]
C393  10uF,6.3V  [603]
C394  10uF,6.3V  [603]
C395  10uF,6.3V  [603]
C396  10uF,6.3V  [603]
C397  10uF,6.3V  [603]
C398  0.1uf,16V  [402]
C399  0.1uf,16V  [402]
C400  10pF,NPO  [402]
Q5  NTA4153N  [SC75]
Q6  BSS138  [SC70]
R282  49.9,1%  [402]
R283  49.9,1%  [402]
R284  49.9,1%  [402]
R285  10K,1%  [402]
R286  100K,1%  [402]
R287  10K,1%  [402]
R288  10K,1%  [402]
R289  10,5%  [402]
R290  0,1%  [402]
R291  0,1%  [402]
R335  10K,1%  [402]
R360  47,1%  [402]
R361  47,1%  [402]
R362  47,1%  [402]
R363  47,1%  [402]
R364  47,1%  [402]
R365  47,1%  [402]
R366  47,1%  [402]
R367  47,1%  [402]
R368  47,1%  [402]
R369  47,1%  [402]
R370  47,1%  [402]
R371  47,1%  [402]
R372  47,1%  [402]
R373  47,1%  [402]
R374  47,1%  [402]
R375  47,1%  [402]
R376  47,1%  [402]
R377  47,1%  [402]
R378  47,1%  [402]
R379  47,1%  [402]
R380  47,1%  [402]
R381  47,1%  [402]
R382  47,1%  [402]
R383  47,1%  [402]
U27  TPS51200_10SON  [DRC10-11x33]
sheet P25_USB & eSATA CONNECTORS
C401  0.1uf,25V,0805  [805]
C402  22uF,25V.LESR  [1210]
C403  100uF,10V  [6032]
C404  100uF,10V  [6032]
C405  0.1uf,16V  [402]
C406  100uF,10V  [6032]
C407  0.1uf,16V  [402]
C408  8.2nF,10V,0201  [201]
C409  22pF  [402]
C410  .001uF,50V  [402]
C411  100uF,10V  [6032]
C412  0.1uf,16V  [402]
C413  100uF,10V  [6032]
C414  0.1uf,16V  [402]
C415  220pF  [402]
C416  0.01uf,16V  [402]
C417  0.01uf,16V  [402]
C418  0.01uf,16V  [402]
C419  DNI  [402]
C420  0.01uf,16V  [402]
C440  22uF,25V.LESR  [1210]
C446  0.1uf,16V  [402]
C447  0.1uf,16V  [402]
C448  0.1uf,16V  [402]
C449  0.1uf,16V  [402]
C450  0.1uf,16V  [402]
C451  0.1uf,16V  [402]
C507  0.001uF,50V  [603]
D24  SK54AFL-TP  [DO221AC]
D25  TPD2EUSB30ADR  [SOT3_DRT_1P0XP8MM]
D26  TPD2EUSB30ADR  [SOT3_DRT_1P0XP8MM]
D27  TPD2EUSB30ADR  [SOT3_DRT_1P0XP8MM]
D28  TPD2EUSB30ADR  [SOT3_DRT_1P0XP8MM]
D29  TPD2EUSB30ADR  [SOT3_DRT_1P0XP8MM]
D30  TPD2EUSB30ADR  [SOT3_DRT_1P0XP8MM]
D31  TPD2EUSB30ADR  [SOT3_DRT_1P0XP8MM]
D32  TPD2EUSB30ADR  [SOT3_DRT_1P0XP8MM]
D33  TPD2EUSB30ADR  [SOT3_DRT_1P0XP8MM]
D34  TPD1E10B06  [2XSON]
D35  TPD1E10B06  [2XSON]
D36  TPD1E10B06  [2XSON]
D37  TPD1E10B06  [2XSON]
D38  TPD2EUSB30ADR  [SOT3_DRT_1P0XP8MM]
L16  4.7uH  [IND130_208X216]
L17  BLM21PG221SN1D  [IND_0805]
L18  BLM21PG221SN1D  [IND_0805]
L19  BLM21PG221SN1D  [IND_0805]
L20  BLM21PG221SN1D  [IND_0805]
P6  eSATA  [ESATA-USB_COMBO_RA]
P13  CONN_USB3.0_A  [USB9RA_2SHIELDED]
P15  GSB311231HR  [USB18RA_4SHIELDED]
R292  10.2K,1%  [402]
R293  25.5K,1%  [402]
R294  30K  [402]
R295  45.3K  [402]
R296  1.91K  [402]
R297  20.5K,1%  [402]
R298  63.4K,1%  [402]
R299  DNI  [402]
R300  DNI  [402]
R435  68  [805]
U28  TPS54531D  [DDA-8]
U29  TPS2561DRC  [DRC10-11X33]
U30  TPS2561DRC  [DRC10-11X33]
sheet P26_PCI, SATA, & SERDES CLOCK
C421  0.1uF/201  [201]
C422  0.1uf,16V  [402]
C423  0.1uf,16V  [402]
C424  0.1uf,16V  [402]
C425  0.1uf,16V  [402]
C426  0.1uf,16V  [402]
C427  0.1uf,16V  [402]
C428  0.1uf,16V  [402]
C429  .001uf,50V  [402]
C430  0.1uf,16V  [402]
C431  10uF,6.3V  [603]
C432  10uF,6.3V  [603]
C433  0.1uf,16V  [402]
C434  0.1uf,16V  [402]
C435  CAP,DNI,0402  [402]
C436  10uF,6.3V  [603]
C437  10uF,6.3V  [603]
C454  0.01uf,16V  [402]
C455  0.01uf,16V  [402]
C456  0.01uf,16V  [402]
C457  0.01uf,16V  [402]
C470  0.1uF/201  [201]
C471  1uF,4V,0201  [201]
L21  FLT_HIFREQ_.47UF  [FLT3SMD_0805-2]
L22  FLT_HIFREQ_.47UF  [FLT3SMD_0805-2]
L23  BLM21PG221SN1D  [IND_0805]
R302  0,1%  [402]
R303  1K,5%  [402]
R308  100,5%  [402]
R309  100K,1%  [402]
R310  100K,1%,DNI  [402]
R311  DNI,0402  [402]
R312  0,1%  [402]
R313  10K,1%  [402]
R398  4.7K  [402]
R399  4.7K  [402]
U7  CDCM9102RHBR  [QFN32]
U31  PI2DBS212_TQFN  [TQFN28S_3P5X5P5P5]
U33  SN75LVCP412A  [QFN20S4X4P5-2]
Y8  25MHz,8pF  [XTAL4_3P2X2P5_SMD]
sheet P27_EXPANSION HEADERS
P16  CONN_30x2_0.8  [HDR2X30SMD_FX18-60P-0P8SV]
P17  CONN_30x2_0.8  [HDR2X30SMD_FX18-60P-0P8SV]
P18  CONN_30x2_0.8  [HDR2X30SMD_FX18-60P-0P8SV]
P19  CONN_30x2_0.8  [HDR2X30SMD_FX18-60P-0P8SV]

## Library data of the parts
D4-D7 = LED_LTST_C150GKT
Q3 Q4 = TRN_DMC56404
R212 R213 R391 R392 = RES_2.2K_1_16W_1%_0402
R215-R218 R398 R399 = RES_4.7K_1_16W_5%_0402
R219-R222 R286 R298 R309 R310 = RES_100K_1_16W_1%_0402
TP6 TP21 = TP
U11 = IC_AM572x_BGA_34
C279-C294 C296-C311 C313-C326 C328-C333 C335-C340 C342-C349 C351-C360 C362-C368 C370-C386 = CAP_0.22uf_X5R_6.3V_20%_0201
R277 R278 = RES_240_1_16W_1%_0402
U25 U26 = MEM_DDR3L_256MBx16_0
C295 C312 C327 C341 C350 C361 C369 C387 C389 C393-C397 C431 C432 C436 C437 = CAP_10uF_X5R_6.3V_20%_0603
C334 C388 C392 C398 C399 C405 C407 C412 C414 C416-C420 C422-C428 C430 C433 C434 C446-C451 C454-C457 = CAP_0.1uF_X7R_16V_10%_0402
C409 C508-C515 = CAP
R279-R284 = RES_49.9K_1_16W_1%_0402
R336-R383 = RES_47_1_16W_1%_0402
C390 C391 C429 C507 = CAP_0.001_X7R_50V_10%_0402
C400 = CAP_10PF_NPO_50V_5%_0402
Q5 = TRN_NTA4153N
Q6 = TRN_BSS138_0
R285 R287 R288 R313 R335 = RES_10K_1_16W_1%_0402
R289 = RES_10_1_10W_5%_0402
R290 R291 R302 = RES_0_1_16W_1%_0402
U27 = IC_TPS51200_10S0N
C401 = CAP_0.1uF_X7R_25V_10%_0805
C402 C440 = CAP_4.7uF_X5R_50V_10%_LESR_1210: Part Number: GRM32ER71E226KE15L
C403 C404 C406 C411 C413 = CAP_100UF_TANT_6.3V_3528-21
C408 = CAP_8.2nF_X5R_10V_10%_0201
C410 = CAP_6.8nF_X7R_50V_10%_0805
C415 = CAP: Part #: C0402C221K5RACTU
D24 = DIO_ZEN_DDZ9678-7_1.8V
D25-D33 D38 = IC_TPD2EUSB30ADRTR_1
D34-D37 = IC_TPD1E05U06
L16 = INDUCTOR
L17-L20 L23 = FERRITE_220_0805
P6 = CONN_11P_eSATA
P13 = CONN_USB3_3.0_A
P15 = CONN_USB3_3.0_A_DUAL
R292 = RES_10.1K_1_16W_1%_0402
R293 R295 = RES_12.1K_1_16W_1%_0402
R294 R296 R435 = RESISTOR
R297 = RES_20.5K_1_16W_1%_0402
R299 R300 = RES_1M_1_16W_1%_0402
U28 = IC_TPS54331,3A_0
U29 U30 = PWR_TPS2560_DRC_0
C421 C470 = CAP_0.1uF_X5R_6.3V_20%_0201
C435 = CAP_DNI_0402
C471 = CAP_1.0UF_X5R_4V_20%_0201
L21 L22 = FLT_HIFREQ_.47UF
R303 = RES_1K_1_16W_5%_0402
R308 = RES_100_1_10W_5%_0402
R311 R312 = RES_DNI_1_16W_1%_0402
U7 = IC_CDCM9102RHBR_0
U31 = IC_PI2DBS212ZHE_TQFN_9
U33 = IC_SN75LVCP412A_1
Y8 = CRYS_25MHz_8pF_4P_3.2x2.5
P16-P19 = CONN_30x2_5.27mm

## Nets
3V3_CDC: C428.1 C429.1 C432.1 C434.1 L23.2 U7.9(VDD3) U7.16(VDD4) U7.18(VDD5) U7.20(VDD6)
5V0: P16.B2 P17.B2 P18.B2 P19.B2 R215.1 R216.1 R217.1 R218.1 ; also on sheet 2 4 16
12V: C402.1 C440.1 P16.B1 P17.B1 P18.B1 P19.B1 U28.2(VIN) ; also on sheet 2
GND: C279.2 C280.2 C283.2 C284.2 C285.2 C286.2 C287.2 C288.2 C289.2 C290.1 C291.2 C292.2 C293.2 C294.2 C295.2 C300.2 C301.2 C302.2 C303.2 C304.2 C305.2 C306.2 C307.2 C308.2 C309.2 C310.2 C311.2 C312.2 C315.2 C316.2 C317.1 C318.1 C319.2 C320.2 C321.2 C322.2 C323.2 C324.2 C325.2 C326.2 C327.2 C335.2 C336.2 C337.2 C338.2 C339.2 C340.2 C341.2 C344.2 C345.2 C346.2 C347.2 C348.2 C349.2 C350.2 C354.2 C355.2 C356.2 C357.2 C359.2 C360.2 C361.2 C363.2 C364.2 C365.2 C366.2 C367.2 C368.2 C369.2 C373.2 C374.2 C375.2 C376.2 C377.2 C378.2 C381.2 C382.2 C383.2 C384.2 C385.2 C386.2 C387.2 C389.2 C390.2 C391.2 C392.2 C393.2 C394.2 C395.2 C396.2 C397.2 C398.2 C399.2 C400.2 C402.2 C403.2 C404.2 C405.2 C406.2 C407.2 C408.2 C409.1 C410.2 C411.2 C412.2 C413.2 C414.2 C415.1 C419.2 C421.2 C428.2 C429.2 C430.2 C431.2 C432.2 C433.2 C434.2 C435.2 C436.2 C437.2 C440.2 C470.2 C471.2 C507.2 C508.2 C509.2 C510.2 C511.2 C512.2 C513.2 C514.2 C515.2 D24.2(ANODE) D25.3(GND) D26.3(GND) D27.3(GND) D28.3(GND) D29.3(GND) D30.3(GND) D31.3(GND) D32.3(GND) D33.3(GND) D34.2(GND) D35.2(GND) D36.2(GND) D37.2(GND) D38.3(GND) L21.2 L22.2 P6.4(GND1) P6.5(GND2) P6.8(GND3) P6.11(GND4) P13.4(GND) P13.7(GNDD) P15.4(GND0) P15.7(GNDD0) P15.13(GND1) P15.16(GNDD1) P16.1 P16.2 P16.28 P16.30 P16.31 P16.32 P16.58 P16.60 P16.A2 P17.1 P17.2 P17.31 P17.32 P17.A2 P18.1 P18.2 P18.31 P18.32 P18.A2 P19.1 P19.4 P19.5 P19.9 P19.10 P19.13 P19.16 P19.19 P19.22 P19.23 P19.26 P19.29 P19.31 P19.32 P19.34 P19.37 P19.38 P19.41 P19.44 P19.47 P19.50 P19.51 P19.54 P19.57 P19.60 P19.A2 Q3.1(4) Q3.4 Q4.1(4) Q4.4 Q5.2(SOURCE) Q6.2(SOURCE) R219.2 R220.2 R221.2 R222.2 R277.2 R278.2 R287.1 R293.1 R296.1 R297.2 R298.2 R299.2 R300.1 R311.2 R312.2 U7.14(GND.1) U7.22(GND.2) U7.33(PWR_PAD) U11.AD13(VSSA_PCIE.1) U11.AE10(VSSA_SATA) U11.AE13(VSSA_PCIE.2) U25.A9(VSS.1) U25.B1(VSSQ.1) U25.B3(VSS.2) U25.B9(VSSQ.2) U25.D1(VSSQ.3) U25.D8(VSSQ.4) U25.E1(VSS.3) U25.E2(VSSQ.5) U25.E8(VSSQ.6) U25.F9(VSSQ.7) U25.G1(VSSQ.8) U25.G8(VSS.4) U25.G9(VSSQ.9) U25.J2(VSSDL) U25.J8(VSS.5) U25.M1(VSS.6) U25.M9(VSS.7) U25.P1(VSS.8) U25.P9(VSS.9) U25.T1(VSS.10) U25.T9(VSS.11) U26.A9(VSS.1) U26.B1(VSSQ.1) U26.B3(VSS.2) U26.B9(VSSQ.2) U26.D1(VSSQ.3) U26.D8(VSSQ.4) U26.E1(VSS.3) U26.E2(VSSQ.5) U26.E8(VSSQ.6) U26.F9(VSSQ.7) U26.G1(VSSQ.8) U26.G8(VSS.4) U26.G9(VSSQ.9) U26.J2(VSSDL) U26.J8(VSS.5) U26.M1(VSS.6) U26.M9(VSS.7) U26.P1(VSS.8) U26.P9(VSS.9) U26.T1(VSS.10) U26.T9(VSS.11) U27.4(PGND) U27.8(GND) U27.11(PWRPAD) U28.7(GND) U28.9(PAD) U29.1(GND) U29.11(PAD) U30.1(GND) U30.11(PAD) U31.1(GND1) U31.10(GND2) U31.12(GND3) U31.14(GND4) U31.20(GND5) U31.25(GND6) U31.27(GND7) U33.3(GND1) U33.13(GND3) U33.17(GND5) U33.18(GND4) U33.19(GND2) U33.21(PAD) Y8.1 Y8.2(NC0) Y8.4(NC1) ; also on sheet 2 3 4 5 6 7 8 9 10 11 12 13 14 15 16 17 18 19 20
GND_EARTH: C415.2 C419.1 P6.14(S1) P6.17(S4) P13.10(SHLD0) P15.20(SHLD1) R299.1 R300.2 ; also on sheet 2 3 8 11 14 15 16 17
VDD_1V8: R302.2 ; also on sheet 4 6 10
VDD_3V3: C389.1 C470.1 C471.1 L22.1 L23.1 P16.A3 P17.A3 P18.A3 P19.A3 R212.1 R213.1 R286.1 R288.2 R294.1 R309.1 R310.1 R313.2 R391.1 R392.1 R398.1 R399.1 U27.10(VIN) U33.6(VCC1) U33.10(VCC4) U33.16(VCC2) U33.20(VCC3) ; also on sheet 2 3 4 6 7 8 9 10 11 12 13 14 15 16 17
VDD_CDC: C430.1 C431.1 C433.1 L22.3 U7.1(VDD2_OUT1) U7.4(VDD1_OUT0)
VDD_DDR: C281.2 C282.2 C283.1 C284.1 C285.1 C286.1 C287.1 C288.1 C289.1 C290.2 C291.1 C292.1 C293.1 C294.1 C295.1 C296.2 C297.2 C298.2 C299.2 C300.1 C301.1 C302.1 C303.1 C304.1 C305.1 C306.1 C307.1 C308.1 C309.1 C310.1 C311.1 C312.1 C313.2 C314.2 C315.1 C316.1 C317.2 C318.2 C319.1 C320.1 C321.1 C322.1 C323.1 C324.1 C325.1 C326.1 C327.1 C328.2 C329.2 C330.2 C331.2 C332.2 C333.2 C334.1 C335.1 C336.1 C337.1 C338.1 C339.1 C340.1 C341.1 C342.2 C343.2 C344.1 C345.1 C346.1 C347.1 C348.1 C349.1 C350.1 C351.2 C352.2 C353.2 C354.1 C355.1 C356.1 C357.1 C358.2 C359.1 C360.1 C361.1 C362.2 C363.1 C364.1 C365.1 C366.1 C367.1 C368.1 C369.1 C370.2 C371.2 C372.2 C373.1 C374.1 C375.1 C376.1 C377.1 C378.1 C379.2 C380.2 C381.1 C382.1 C383.1 C384.1 C385.1 C386.1 C387.1 C388.1 C391.1 C392.1 C393.1 C394.1 C508.1 C509.1 C510.1 C511.1 C512.1 C513.1 C514.1 C515.1 R285.1 U25.A1(VDDQ.1) U25.A8(VDDQ.2) U25.B2(VDD.1) U25.C1(VDDQ.3) U25.C9(VDDQ.4) U25.D2(VDDQ.5) U25.D9(VDD.2) U25.E9(VDDQ.6) U25.F1(VDDQ.7) U25.G7(VDD.3) U25.H2(VDDQ.8) U25.H9(VDDQ.9) U25.K2(VDDL) U25.K8(VDD.4) U25.N1(VDD.5) U25.N9(VDD.6) U25.R1(VDD.7) U25.R9(VDD.8) U26.A1(VDDQ.1) U26.A8(VDDQ.2) U26.B2(VDD.1) U26.C1(VDDQ.3) U26.C9(VDDQ.4) U26.D2(VDDQ.5) U26.D9(VDD.2) U26.E9(VDDQ.6) U26.F1(VDDQ.7) U26.G7(VDD.3) U26.H2(VDDQ.8) U26.H9(VDDQ.9) U26.K2(VDDL) U26.K8(VDD.4) U26.N1(VDD.5) U26.N9(VDD.6) U26.R1(VDD.7) U26.R9(VDD.8) U27.2(VLDOIN) ; also on sheet 5 10 18 20
VIN3A_CLKO: P16.50 ; also on sheet 13
VIN3A_D0: P16.51 ; also on sheet 13
VIN3A_D1: P16.52 ; also on sheet 13
VIN3A_D2: P16.16 ; also on sheet 13
VIN3A_D3: P16.22 ; also on sheet 13
VIN3A_D4: P16.15 ; also on sheet 13
VIN3A_D5: P16.18 ; also on sheet 13
VIN3A_D6: P16.53 ; also on sheet 13
VIN3A_D7: P16.54 ; also on sheet 13
VIN3A_D8: P16.23 ; also on sheet 13
VIN3A_D9: P16.57 ; also on sheet 13
VIN3A_D10: P16.56 ; also on sheet 13
VIN3A_D11: P16.55 ; also on sheet 13
VIN3A_D12: P16.24 ; also on sheet 13
VIN3A_D13: P16.26 ; also on sheet 13
VIN3A_D14: P16.27 ; also on sheet 13
VIN3A_D15: P16.25 ; also on sheet 13
VIN3A_D16: P16.36 ; also on sheet 13
VIN3A_D17: P16.43 ; also on sheet 13
VIN3A_D18: P16.12 ; also on sheet 13
VIN3A_D19: P16.42 ; also on sheet 13
VIN3A_D20: P16.10 ; also on sheet 13
VIN3A_D21: P16.13 ; also on sheet 13
VIN3A_D22: P16.6 ; also on sheet 13
VIN3A_D23: P16.45 ; also on sheet 13
VIN3A_DEO: P16.14 ; also on sheet 13
VIN3A_FLD: P16.44 ; also on sheet 13
VIN3A_HSYNC: P16.9 ; also on sheet 13
VIN3A_VSYNC: P16.37 ; also on sheet 13
BATEN0: U29.4(EN1) ; also on sheet 14
BATEN1: U29.5(EN2) ; also on sheet 14
BATEN2: U30.4(EN1) ; also on sheet 14
BATEN3: U30.5(EN2) ; also on sheet 14
CDC_CAP1: C436.1 U7.19(REG_CAP1)
CDC_CAP2: C437.1 U7.17(REG_CAP2)
CDC_OE: R313.1 U7.7(OE)
CDC_OS1: R310.2 R312.1 U7.10(OS1)
CDC_OS2: R309.2 R311.1 U7.11(OS0)
CDC_OSCIN: C435.1 U7.21(XIN) Y8.3
CLKOUT3: P17.41 ; also on sheet 13
CON.PCIE_RXN0: P19.25 U11.AG13(PCIE_RXN0)
CON.PCIE_RXN1: P19.18 U11.AG11(PCIE_RXN1)
CON.PCIE_RXP0: P19.24 U11.AH13(PCIE_RXP0)
CON.PCIE_RXP1: P19.17 U11.AH11(PCIE_RXP1)
CON.PCIE_TXN0: C423.2 P19.28
CON.PCIE_TXN1: C425.2 P19.21
CON.PCIE_TXP0: C422.2 P19.27
CON.PCIE_TXP1: C424.2 P19.20
CONN_SATA_RXN: C418.2 U33.12(RX2N)
CONN_SATA_RXP: C420.2 U33.11(RX2P)
CONN_SATA_TXN: C417.2 U33.14(TX1N)
CONN_SATA_TXP: C416.1 U33.15(TX1P)
DCAN1_RX: P17.20 U11.G19(DCAN1_RX)
DCAN1_TX: P17.50 U11.G20(DCAN1_TX)
DDR1_A0: R364.1 ; also on sheet 18 20
DDR1_A1: R365.1 ; also on sheet 18 20
DDR1_A2: R371.1 ; also on sheet 18 20
DDR1_A3: R376.1 ; also on sheet 18 20
DDR1_A4: R366.1 ; also on sheet 18 20
DDR1_A5: R367.1 ; also on sheet 18 20
DDR1_A6: R381.1 ; also on sheet 18 20
DDR1_A7: R369.1 ; also on sheet 18 20
DDR1_A8: R383.1 ; also on sheet 18 20
DDR1_A9: R368.1 ; also on sheet 18 20
DDR1_A10: R373.1 ; also on sheet 18 20
DDR1_A11: R380.1 ; also on sheet 18 20
DDR1_A12: R379.1 ; also on sheet 18 20
DDR1_A13: R370.1 ; also on sheet 18 20
DDR1_A14: R382.1 ; also on sheet 18 20
DDR1_A15: R375.1 ; also on sheet 18 20
DDR1_BA0: R363.1 ; also on sheet 18 20
DDR1_BA1: R377.1 ; also on sheet 18 20
DDR1_BA2: R378.1 ; also on sheet 18 20
DDR1_CASN: R361.1 ; also on sheet 18 20
DDR1_CKE: R282.1 ; also on sheet 18 20
DDR1_CLK0: R284.1 ; also on sheet 18 20
DDR1_CLK0N: R283.1 ; also on sheet 18 20
DDR1_CLK_TERM: C388.2 R283.2 R284.2
DDR1_CSN0: R362.1 ; also on sheet 18 20
DDR1_ODT0: R360.1 ; also on sheet 18 20
DDR1_RASN: R372.1 ; also on sheet 18 20
DDR1_WEN: R374.1 ; also on sheet 18 20
DDR2_A0: R355.1 U25.N3(A0) U26.N3(A0) ; also on sheet 19
DDR2_A1: R356.1 U25.P7(A1) U26.P7(A1) ; also on sheet 19
DDR2_A2: R346.1 U25.P3(A2) U26.P3(A2) ; also on sheet 19
DDR2_A3: R344.1 U25.N2(A3) U26.N2(A3) ; also on sheet 19
DDR2_A4: R347.1 U25.P8(A4) U26.P8(A4) ; also on sheet 19
DDR2_A5: R345.1 U25.P2(A5) U26.P2(A5) ; also on sheet 19
DDR2_A6: R338.1 U25.R8(A6) U26.R8(A6) ; also on sheet 19
DDR2_A7: R358.1 U25.R2(A7) U26.R2(A7) ; also on sheet 19
DDR2_A8: R359.1 U25.T8(A8) U26.T8(A8) ; also on sheet 19
DDR2_A9: R336.1 U25.R3(A9) U26.R3(A9) ; also on sheet 19
DDR2_A10: R340.1 U25.L7(A10) U26.L7(A10) ; also on sheet 19
DDR2_A11: R337.1 U25.R7(A11) U26.R7(A11) ; also on sheet 19
DDR2_A12: R354.1 U25.N7(A12) U26.N7(A12) ; also on sheet 19
DDR2_A13: R357.1 U25.T3(A13) U26.T3(A13) ; also on sheet 19
DDR2_A14: R339.1 U25.T7(A14) U26.T7(A14) ; also on sheet 19
DDR2_A15: R342.1 U25.M7(NC.M7/A15) U26.M7(NC.M7/A15) ; also on sheet 19
DDR2_BA0: R350.1 U25.M2(BA0) U26.M2(BA0) ; also on sheet 19
DDR2_BA1: R353.1 U25.N8(BA1) U26.N8(BA1) ; also on sheet 19
DDR2_BA2: R352.1 U25.M3(BA2) U26.M3(BA2) ; also on sheet 19
DDR2_CASN: R349.1 U25.K3(CAS#) U26.K3(CAS#) ; also on sheet 19
DDR2_CKE: R348.1 U25.K9(CKE) U26.K9(CKE) ; also on sheet 19
DDR2_CLK0: R281.1 U25.J7(CK) U26.J7(CK) ; also on sheet 19
DDR2_CLK0N: R280.1 U25.K7(CK#) U26.K7(CK#) ; also on sheet 19
DDR2_CLK_TRM: C334.2 R280.2 R281.2
DDR2_CSN0: R351.1 U25.L2(CS#) U26.L2(CS#) ; also on sheet 19
DDR2_D0: U25.D7(DQ8) ; also on sheet 19
DDR2_D1: U25.C2(DQ11) ; also on sheet 19
DDR2_D2: U25.A3(DQ15) ; also on sheet 19
DDR2_D3: U25.B8(DQ14) ; also on sheet 19
DDR2_D4: U25.A2(DQ13) ; also on sheet 19
DDR2_D5: U25.C3(DQ9) ; also on sheet 19
DDR2_D6: U25.A7(DQ12) ; also on sheet 19
DDR2_D7: U25.C8(DQ10) ; also on sheet 19
DDR2_D8: U25.E3(DQ0) ; also on sheet 19
DDR2_D9: U25.H3(DQ4) ; also on sheet 19
DDR2_D10: U25.H8(DQ5) ; also on sheet 19
DDR2_D11: U25.G2(DQ6) ; also on sheet 19
DDR2_D12: U25.H7(DQ7) ; also on sheet 19
DDR2_D13: U25.F2(DQ2) ; also on sheet 19
DDR2_D14: U25.F8(DQ3) ; also on sheet 19
DDR2_D15: U25.F7(DQ1) ; also on sheet 19
DDR2_D16: U26.D7(DQ8) ; also on sheet 19
DDR2_D17: U26.C8(DQ10) ; also on sheet 19
DDR2_D18: U26.A2(DQ13) ; also on sheet 19
DDR2_D19: U26.C2(DQ11) ; also on sheet 19
DDR2_D20: U26.C3(DQ9) ; also on sheet 19
DDR2_D21: U26.B8(DQ14) ; also on sheet 19
DDR2_D22: U26.A3(DQ15) ; also on sheet 19
DDR2_D23: U26.A7(DQ12) ; also on sheet 19
DDR2_D24: U26.E3(DQ0) ; also on sheet 19
DDR2_D25: U26.H8(DQ5) ; also on sheet 19
DDR2_D26: U26.H7(DQ7) ; also on sheet 19
DDR2_D27: U26.F7(DQ1) ; also on sheet 19
DDR2_D28: U26.F8(DQ3) ; also on sheet 19
DDR2_D29: U26.H3(DQ4) ; also on sheet 19
DDR2_D30: U26.F2(DQ2) ; also on sheet 19
DDR2_D31: U26.G2(DQ6) ; also on sheet 19
DDR2_DQM0: U25.D3(UDM) ; also on sheet 19
DDR2_DQM1: U25.E7(LDM) ; also on sheet 19
DDR2_DQM2: U26.D3(UDM) ; also on sheet 19
DDR2_DQM3: U26.E7(LDM) ; also on sheet 19
DDR2_DQS0: U25.C7(UDQS) ; also on sheet 19
DDR2_DQS1: U25.F3(LDQS) ; also on sheet 19
DDR2_DQS2: U26.C7(UDQS) ; also on sheet 19
DDR2_DQS3: U26.F3(LDQS) ; also on sheet 19
DDR2_DQSN0: U25.B7(UDQS#) ; also on sheet 19
DDR2_DQSN1: U25.G3(LDQS#) ; also on sheet 19
DDR2_DQSN2: U26.B7(UDQS#) ; also on sheet 19
DDR2_DQSN3: U26.G3(LDQS#) ; also on sheet 19
DDR2_ODT0: R341.1 U25.K1(ODT) U26.K1(ODT) ; also on sheet 19
DDR2_RASN: R279.1 U25.J3(RAS#) U26.J3(RAS#) ; also on sheet 19
DDR2_RST: TP21.1 U25.T2(RSTn) U26.T2(RSTn) ; also on sheet 19
DDR2_WEN: R343.1 U25.L3(WE#) U26.L3(WE#) ; also on sheet 19
DDR_REFIN: C390.1 R285.2 R287.2 U27.1(REFIN)
DDR_VREF_OFFn: Q5.1(GATE) R288.1 U27.7(EN) ; also on sheet 18
DDR_VREFSTL1: R290.2 ; also on sheet 18 20
DDR_VREFSTL2: C279.1 C280.1 C281.1 C282.1 R291.2 U25.H1(VREFDQ) U25.M8(VREFCA) U26.H1(VREFDQ) U26.M8(VREFCA) ; also on sheet 19
DMA_EVT1: P16.35 ; also on sheet 13
DMA_EVT3: P16.11 ; also on sheet 13
DMA_EVT4: P16.17 ; also on sheet 13
EHRPWM2_TRIPZONE_INPUT: P18.6 U11.F6(EHRPWM2_TRIPZONE_INPUT)
EHRPWM2A: P17.5 U11.AC5(EHRPWM2A)
EHRPWM2B: P18.44 U11.D3(EHRPWM2B)
ENET0_INTn: U11.D26(GPIO7_27) ; also on sheet 11
ENET1_INTn: U11.D28(GPIO7_26) ; also on sheet 12
eSATA_R+: C420.1 P6.10(B+)
eSATA_R-: C418.1 P6.9(B-)
eSATA_T+: C416.2 P6.6(A+)
eSATA_T-: C417.1 P6.7(A-)
EXP_SATA_RXN: P19.7 U31.22(B1-)
EXP_SATA_RXP: P19.8 U31.21(B1+)
EXP_SATA_TXN: P19.36 U31.23(B0-)
EXP_SATA_TXP: P19.35 U31.24(B0+)
EXT_WAKE: P18.35 ; also on sheet 4 8
GPIO2_2: P16.46 ; also on sheet 13
GPIO2_3: P16.7 ; also on sheet 13
GPIO2_4: P16.40 ; also on sheet 13
GPIO2_5: P16.38 ; also on sheet 13
GPIO2_6: P16.39 ; also on sheet 13
GPIO2_8: P16.8 ; also on sheet 13
GPIO2_17: P16.48 ; also on sheet 13
GPIO2_19: P16.41 ; also on sheet 13
GPIO2_20: P16.49 ; also on sheet 13
GPIO2_23: P16.21 ; also on sheet 13
GPIO2_24: P16.47 ; also on sheet 13
GPIO2_25: P16.19 ; also on sheet 13
GPIO2_28: P16.20 ; also on sheet 13
GPIO2_31: P19.55 U11.AH7(GPIO2_31)
GPIO3_6: P19.56 U11.AG7(GPIO3_6)
GPIO3_7: P19.52 U11.AH6(GPIO3_7)
GPIO3_8: P19.45 U11.AH3(GPIO3_8)
GPIO3_9: P19.48 U11.AH5(GPIO3_9)
GPIO3_10: P19.53 U11.AG6(GPIO3_10)
GPIO3_11: P19.14 U11.AH4(GPIO3_11)
GPIO3_12: P19.15 U11.AG4(GPIO3_12)
GPIO3_14: P19.46 U11.AG3(GPIO3_14)
GPIO3_15: P19.49 U11.AG5(GPIO3_15)
GPIO3_16: P19.42 U11.AF2(GPIO3_16)
GPIO3_18: P19.43 U11.AF3(GPIO3_18)
GPIO3_20: P19.11 U11.AF1(GPIO3_20)
GPIO3_23: P19.39 U11.AE1(GPIO3_23)
GPIO3_24: P19.12 U11.AE2(GPIO3_24)
GPIO3_26: P19.40 U11.AD2(GPIO3_26)
GPIO3_28: P18.11 U11.E1(GPIO3_28)
GPIO3_29: P18.9 U11.G2(GPIO3_29)
GPIO3_30: P18.36 U11.H7(GPIO3_30)
GPIO4_7: P18.43 U11.C1(GPIO4_7)
GPIO4_8: P18.39 U11.E4(GPIO4_8)
GPIO4_9: P18.38 U11.F5(GPIO4_9)
GPIO4_10: P18.7 U11.E6(GPIO4_10)
GPIO4_17: P16.3 U11.A12(GPIO4_17)
GPIO5_4: P17.47 ; also on sheet 13
GPIO5_5: P17.17 ; also on sheet 13
GPIO5_6: P17.45 ; also on sheet 13
GPIO5_7: P17.15 ; also on sheet 13
GPIO5_8: P17.55 ; also on sheet 13
GPIO5_9: P17.25 ; also on sheet 13
GPIO5_10: P16.34 U11.B12(GPIO5_10)
GPIO5_11: P16.4 U11.A11(GPIO5_11)
GPIO5_12: P16.33 U11.B13(GPIO5_12)
GPIO5_18: P18.59 U11.V2(UART3_RXD)
GPIO5_19: P18.29 U11.Y1(UART3_TXD)
GPIO6_11: P17.3 U11.AB4(GPIO6_11)
GPIO6_18: P17.58 U11.E17(GPIO6_18)
GPIO6_19: P17.28 ; also on sheet 13
GPIO7_7: P17.51 U11.A25(GPIO7_7)
I2C1_SCL: R212.2 U11.C20(I2C1_SCL) ; also on sheet 2 3 7 15
I2C1_SDA: R213.2 U11.C21(I2C1_SDA) ; also on sheet 2 3 7 15
I2C3_SCL: R392.2 U11.D14(I2C3_SCL) ; also on sheet 4 14
I2C3_SDA: R391.2 U11.C14(I2C3_SDA) ; also on sheet 4 14
I2C4_SCL: P17.46 ; also on sheet 13
I2C4_SDA: P17.53 ; also on sheet 13
I2C5_SCL: P18.4 U11.F12(I2C5_SCL)
I2C5_SDA: P18.3 U11.G12(I2C5_SDA)
LEDAA: D4.2(A) R215.2
LEDAC: D4.1(C) Q3.6(3)
LEDBA: D5.2(A) R216.2
LEDBC: D5.1(C) Q3.3
LEDCA: D6.2(A) R217.2
LEDCC: D6.1(C) Q4.6(3)
LEDDA: D7.2(A) R218.2
LEDDC: D7.1(C) Q4.3
MCASP2_ACLKR: P17.44 ; also on sheet 13
MCASP2_AXR0: P17.54 ; also on sheet 13
MCASP2_AXR1: P17.23 ; also on sheet 13
MCASP2_AXR2: P17.18 U11.C15(MCASP2_AXR2)
MCASP2_AXR3: P17.22 U11.A16(MCASP2_AXR3)
MCASP2_AXR4: P17.16 ; also on sheet 13
MCASP2_AXR5: P17.24 ; also on sheet 13
MCASP2_AXR6: P17.26 ; also on sheet 13
MCASP2_AXR7: P17.56 ; also on sheet 13
MCASP2_CLKX: P17.21 U11.A19(MCASP2_ACLKX)
MCASP2_FSR: P17.57 ; also on sheet 13
MCASP2_FSX: P17.52 U11.A18(MCASP2_FSX)
MCASP7_AXR0: P16.5 U11.E14(MCASP7_AXR0)
MCASP7_AXR1: P17.49 U11.A13(MCASP7_AXR1)
MCASP7_CLKX: P17.48 U11.G14(MCASP7_CLKX)
MCASP7_FSX: P17.19 U11.F14(MCASP7_FSX)
MMC3_CLK: P17.34 ; also on sheet 17
MMC3_CMD: P17.4 ; also on sheet 17
MMC3_DAT0: P17.7 ; also on sheet 17
MMC3_DAT1: P17.36 ; also on sheet 17
MMC3_DAT2: P17.8 ; also on sheet 17
MMC3_DAT3: P17.33 ; also on sheet 17
MMC3_DAT4: P17.37 ; also on sheet 17
MMC3_DAT5: P17.35 ; also on sheet 17
MMC3_DAT6: P17.38 ; also on sheet 17
MMC3_DAT7: P17.6 ; also on sheet 17
OC0: U29.10(~{FAULT1}) ; also on sheet 14
OC1: U29.6(~{FAULT2}) ; also on sheet 14
OC2: U30.10(~{FAULT1}) ; also on sheet 14
OC3: U30.6(~{FAULT2}) ; also on sheet 14
PCI_CONN_REFN: P19.58 U7.2(OUT1N)
PCI_CONN_REFP: P19.59 U7.3(OUT1P)
PCIE_TXN0: C423.1 U11.AG14(PCIE_TXN0)
PCIE_TXN1: C425.1 U11.AG12(PCIE_TXN1)
PCIE_TXP0: C422.1 U11.AH14(PCIE_TXP0)
PCIE_TXP1: C424.1 U11.AH12(PCIE_TXP1)
PR1_UART0_CTSn: P18.40 U11.G1(PR1_UART0_CTSn)
PR1_UART0_RTSn: P18.37 U11.G6(PR1_UART0_RTSn)
PR1_UART0_RXD: P18.41 U11.F2(PR1_UART0_RXD)
PR1_UART0_TXD: P18.10 U11.F3(PR1_UART0_TXD)
PS_3V3: R335.1 ; also on sheet 2 3 4 5 6 8
PWRON: P18.5 ; also on sheet 3
RDRXN: C456.2 U33.4(TX2N)
RDRXP: C455.2 U33.5(TX2P)
RDTXN: C457.2 U33.2(RX1N)
RDTXP: C454.1 U33.1(RX1P)
RESETIN: P18.34 ; also on sheet 8
RSTOUTn: P18.33 U7.12(RSTn) ; also on sheet 3 8 15 17
RXN_MUXC: C456.1 U31.16(C1-)
RXP_MUXC: C455.1 U31.15(C1+)
SAT_RXN: U11.AH9(SATA1_RXN0) U31.6(A1-)
SAT_RXP: U11.AG9(SATA1_RXP0) U31.7(A1+)
SAT_TXN: U11.AG10(SATA1_TXN0) U31.5(A0-)
SAT_TXP: U11.AH10(SATA1_TXP0) U31.4(A0+)
SATA_SEL: P19.6 R303.2 U31.3(SEL)
SERDES_CLKN: C426.2 R308.1 U11.AH15(LJCB_CLKN)
SERDES_CLKP: C427.2 R308.2 U11.AG15(LJCB_CLKP)
SERDES_IN_REFN: C426.1 U7.5(OUT0N)
SERDES_IN_REFP: C427.1 U7.6(OUT0P)
TIMER1: P17.42 ; also on sheet 13
TIMER2: P17.13 ; also on sheet 13
TIMER3: P17.12 ; also on sheet 13
TMP102_ALERT: U11.G17(GPIO7_16) ; also on sheet 2
TX1+: C449.2 D29.1(D+) P15.9(TX0+)
TX1-: C448.2 D29.2(D-) P15.8(TX0-)
TX2+: C451.2 D31.1(D+) P15.18(TX1+)
TX2-: C450.2 D31.2(D-) P15.17(TX1-)
TX+: C447.2 D26.1(D+) P13.9(TX+)
TX-: C446.2 D26.2(D-) P13.8(TX-)
TXN_MUXC: C457.1 U31.17(C0-)
TXP_MUXC: C454.2 U31.18(C0+)
U28_1: C401.2 U28.1(BOOT)
U28_3: R294.2 R297.1 U28.3(EN)
U28_4: C408.1 U28.4(SS)
U28_6: C409.2 R295.1 U28.6(COMP)
U28_8: C401.1 D24.1(CATHODE) L16.1 R435.1 U28.8(PH)
U28_RC: C410.1 R295.2
U29_7: R293.2 U29.7(ILIM)
U30_7: R298.1 U30.7(ILIM)
U31_1V8: C421.1 L21.1 R303.1 U31.9(VDD1) U31.11(VDD2) U31.13(VDD3) U31.19(VDD4) U31.26(VDD5) U31.28(VDD6)
U31_VDD: L21.3 R302.1
UART1_RXD: P18.60 U11.C26(UART1_TXD)
UART1_TXD: P18.30 U11.B27(UART1_RXD)
UART3_RXD: U11.D27(GPIO1_16) ; also on sheet 15
UART3_TXD: U11.C28(GPIO1_17) ; also on sheet 15
UART8_CTSN: P17.11 ; also on sheet 13
UART8_RTSN: P17.14 ; also on sheet 13
UART8_RXD: P17.43 ; also on sheet 13
UART8_TXD: P17.27 ; also on sheet 13
UART9_CTSN: P17.40 ; also on sheet 13
UART9_RTSN: P17.39 ; also on sheet 13
UART9_RXD: P17.10 ; also on sheet 13
UART9_TXD: P17.9 ; also on sheet 13
UART10_CTSn: P18.13 U11.D2(UART10_CTSn)
UART10_RTSn: P18.8 U11.F4(UART10_RTSn)
UART10_RXD: P18.12 U11.D1(UART10_RXD)
UART10_TXD: P18.42 U11.E2(UART10_TXD)
USB1V: C404.1 C405.1 L18.1 U29.9(OUT1)
USB1VBUS: D35.1(IO) L18.2 P13.1(USBVDD)
USB2V: C406.1 C407.1 L17.1 U29.8(OUT2)
USB2VBUS: D34.1(IO) L17.2 P15.1(VBUS0)
USB3V: C411.1 C412.1 L19.1 U30.9(OUT1)
USB3VBUS: D36.1(IO) L19.2 P15.10(VBUS1)
USB4V: C413.1 C414.1 L20.1 U30.8(OUT2)
USB4VBUS: D37.1(IO) L20.2 P6.1(VBUS0)
USB_5V: C403.1 L16.2 R292.1 U29.2(IN1) U29.3(IN2) U30.2(IN1) U30.3(IN2)
USB_DM0: D27.1(D+) P13.2(D-) ; also on sheet 14
USB_DM1: D30.2(D-) P15.2(D0-) ; also on sheet 14
USB_DM2: D33.2(D-) P15.11(D1-) ; also on sheet 14
USB_DM3: D32.2(D-) P6.2(D-) ; also on sheet 14
USB_DP0: D27.2(D-) P13.3(D+) ; also on sheet 14
USB_DP1: D30.1(D+) P15.3(D0+) ; also on sheet 14
USB_DP2: D33.1(D+) P15.12(D1+) ; also on sheet 14
USB_DP3: D32.1(D+) P6.3(D+) ; also on sheet 14
USB_RXM0: D25.2(D-) P13.5(RX-) ; also on sheet 14
USB_RXM1: D28.2(D-) P15.5(RX0-) ; also on sheet 14
USB_RXM2: D38.2(D-) P15.14(RX1-) ; also on sheet 14
USB_RXP0: D25.1(D+) P13.6(RX+) ; also on sheet 14
USB_RXP1: D28.1(D+) P15.6(RX0+) ; also on sheet 14
USB_RXP2: D38.1(D+) P15.15(RX1+) ; also on sheet 14
USB_SNS: R292.2 R296.2 U28.5(VSNS)
USB_TXM0: C446.1 ; also on sheet 14
USB_TXM1: C448.1 ; also on sheet 14
USB_TXM2: C450.1 ; also on sheet 14
USB_TXP0: C447.1 ; also on sheet 14
USB_TXP1: C449.1 ; also on sheet 14
USB_TXP2: C451.1 ; also on sheet 14
USR0: Q3.2(5) R219.1 U11.F16(GPIO7_8)
USR1: Q3.5 R220.1 U11.B25(GPIO7_9)
USR2: Q4.2(5) R221.1 U11.A26(GPIO7_14)
USR3: Q4.5 R222.1 U11.B22(GPIO7_15)
VOUT1_CLK: P18.57 ; also on sheet 13
VOUT1_D0: P18.25 ; also on sheet 13
VOUT1_D1: P18.55 ; also on sheet 13
VOUT1_D2: P18.54 ; also on sheet 13
VOUT1_D3: P18.26 ; also on sheet 13
VOUT1_D4: P18.48 ; also on sheet 13
VOUT1_D5: P18.49 ; also on sheet 13
VOUT1_D6: P18.45 ; also on sheet 13
VOUT1_D7: P18.46 ; also on sheet 13
VOUT1_D8: P18.47 ; also on sheet 13
VOUT1_D9: P18.56 ; also on sheet 13
VOUT1_D10: P18.16 ; also on sheet 13
VOUT1_D11: P18.18 ; also on sheet 13
VOUT1_D12: P18.20 ; also on sheet 13
VOUT1_D13: P18.15 ; also on sheet 13
VOUT1_D14: P18.17 ; also on sheet 13
VOUT1_D15: P18.14 ; also on sheet 13
VOUT1_D16: P18.50 ; also on sheet 13
VOUT1_D17: P18.51 ; also on sheet 13
VOUT1_D18: P18.21 ; also on sheet 13
VOUT1_D19: P18.22 ; also on sheet 13
VOUT1_D20: P18.19 ; also on sheet 13
VOUT1_D21: P18.23 ; also on sheet 13
VOUT1_D22: P18.52 ; also on sheet 13
VOUT1_D23: P18.24 ; also on sheet 13
VOUT1_DE: P18.53 ; also on sheet 13
VOUT1_HSYNC: P18.27 ; also on sheet 13
VOUT1_VSYNC: P18.28 ; also on sheet 13
VTT: C296.1 C297.1 C298.1 C299.1 C313.1 C314.1 C328.1 C329.1 C330.1 C331.1 C332.1 C333.1 C342.1 C343.1 C351.1 C352.1 C353.1 C358.1 C362.1 C370.1 C371.1 C372.1 C379.1 C380.1 C395.1 C396.1 C397.1 C398.1 Q6.3(DRAIN) R279.2 R282.2 R289.1 R336.2 R337.2 R338.2 R339.2 R340.2 R341.2 R342.2 R343.2 R344.2 R345.2 R346.2 R347.2 R348.2 R349.2 R350.2 R351.2 R352.2 R353.2 R354.2 R355.2 R356.2 R357.2 R358.2 R359.2 R360.2 R361.2 R362.2 R363.2 R364.2 R365.2 R366.2 R367.2 R368.2 R369.2 R370.2 R371.2 R372.2 R373.2 R374.2 R375.2 R376.2 R377.2 R378.2 R379.2 R380.2 R381.2 R382.2 R383.2 U27.3(VO)
VTT_PGOOD: R286.2 U27.9(PGOOD)
VTT_REFOUT: C400.1 R289.2 U27.5(VOSNS)
VTT_TRAN: Q5.3(DRAIN) Q6.1(GATE) R335.2
VTT_VOSNS: C399.1 R290.1 R291.1 U27.6(REFOUT)
ZQ2_HI: R278.1 U26.L8(ZQ)
ZQ2_LO: R277.1 U25.L8(ZQ)
N28155188: TP6.1 U11.K14(RSVD4)
N28826254: R398.2 U33.9(PE1)
N28826261: R399.2 U33.8(PE2)
N30587344: C507.1 R435.2

Not connected (* = marked no-connect by the designer): P6 12(M1)* 13(M2)* 15(S2)* 16(S3)*; P13 11(SHLD1)*; P15 19(SHLD0)* 21(SHLD2)* 22(SHLD3)*; P16 29* 59* A1* A4*; P17 29* 30* 59* 60* A1* A4*; P18 58* A1* A4*; P19 2* 3* 30* 33* A1* A4*; U7 8(NC.8)* 13(NC.13)* 15(NC.15)* 23(OSCOUT)* 24(NC.24)* 25(NC.25)* 26(NC.26)* 27(NC.27)* 28(NC.28)* 29(NC.29) 30(NC.30)* 31(NC.31)* 32(NC.32)*; U11 A27(RSVD2)* AA1(MLBP_DAT_P)* AA2(MLBP_DAT_n)* AB1(MLBP_CLK_P)* AB2(MLBP_CLK_n)* AC1(MLBP_SIG_P)* AC2(MLBP_SIG_n)* AD3(GPIO3_27)* AD8(GPIO3_5)* AD9(GPIO3_0)* AE3(GPIO3_21)* AE5(GPIO3_22)* AE6(GPIO3_25)* AE8(GPIO3_4)* AE9(GPIO3_2)* AF4(GPIO3_19)* AF6(GPIO3_17)* AF8(GPIO3_3)* AF9(GPIO3_1)* AG2(GPIO3_13)* B28(RSVD1)* Y5(RSVD5)* Y9(GPIO6_28)* Y10(RSVD3)*; U25 J1(NC.J1)* J9(NC.J9)* L1(NC.L1)* L9(NC.L9)*; U26 J1(NC.J1)* J9(NC.J9)* L1(NC.L1)* L9(NC.L9)*; U31 2(NC)* 8(NC1)*; U33 7(EN)*

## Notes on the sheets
sheet 21
- Preliminary Information - Subject to change
sheet 24
- 12VDC TO 5VDC 4A
- ACTIVATES AT 3.1V.
sheet 25
- OUTCLOCK = 100mHZ
sheet 26
- 1.8V
- Copyright 2015 Embedded Product Design, LLC
sheet 27
- User LED's
- USR0
- USR1
- USR2
- USR3
